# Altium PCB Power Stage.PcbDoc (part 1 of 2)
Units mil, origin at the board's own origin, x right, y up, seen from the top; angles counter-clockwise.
Board outline 9000 x 8000 mil, 6 copper layers (Top Layer, Layer 1, Layer 2, Layer 3, Layer 4, Bottom Layer), stack 92.2 mil thick; 168 components, 72 nets, 534 pads, 347 vias.
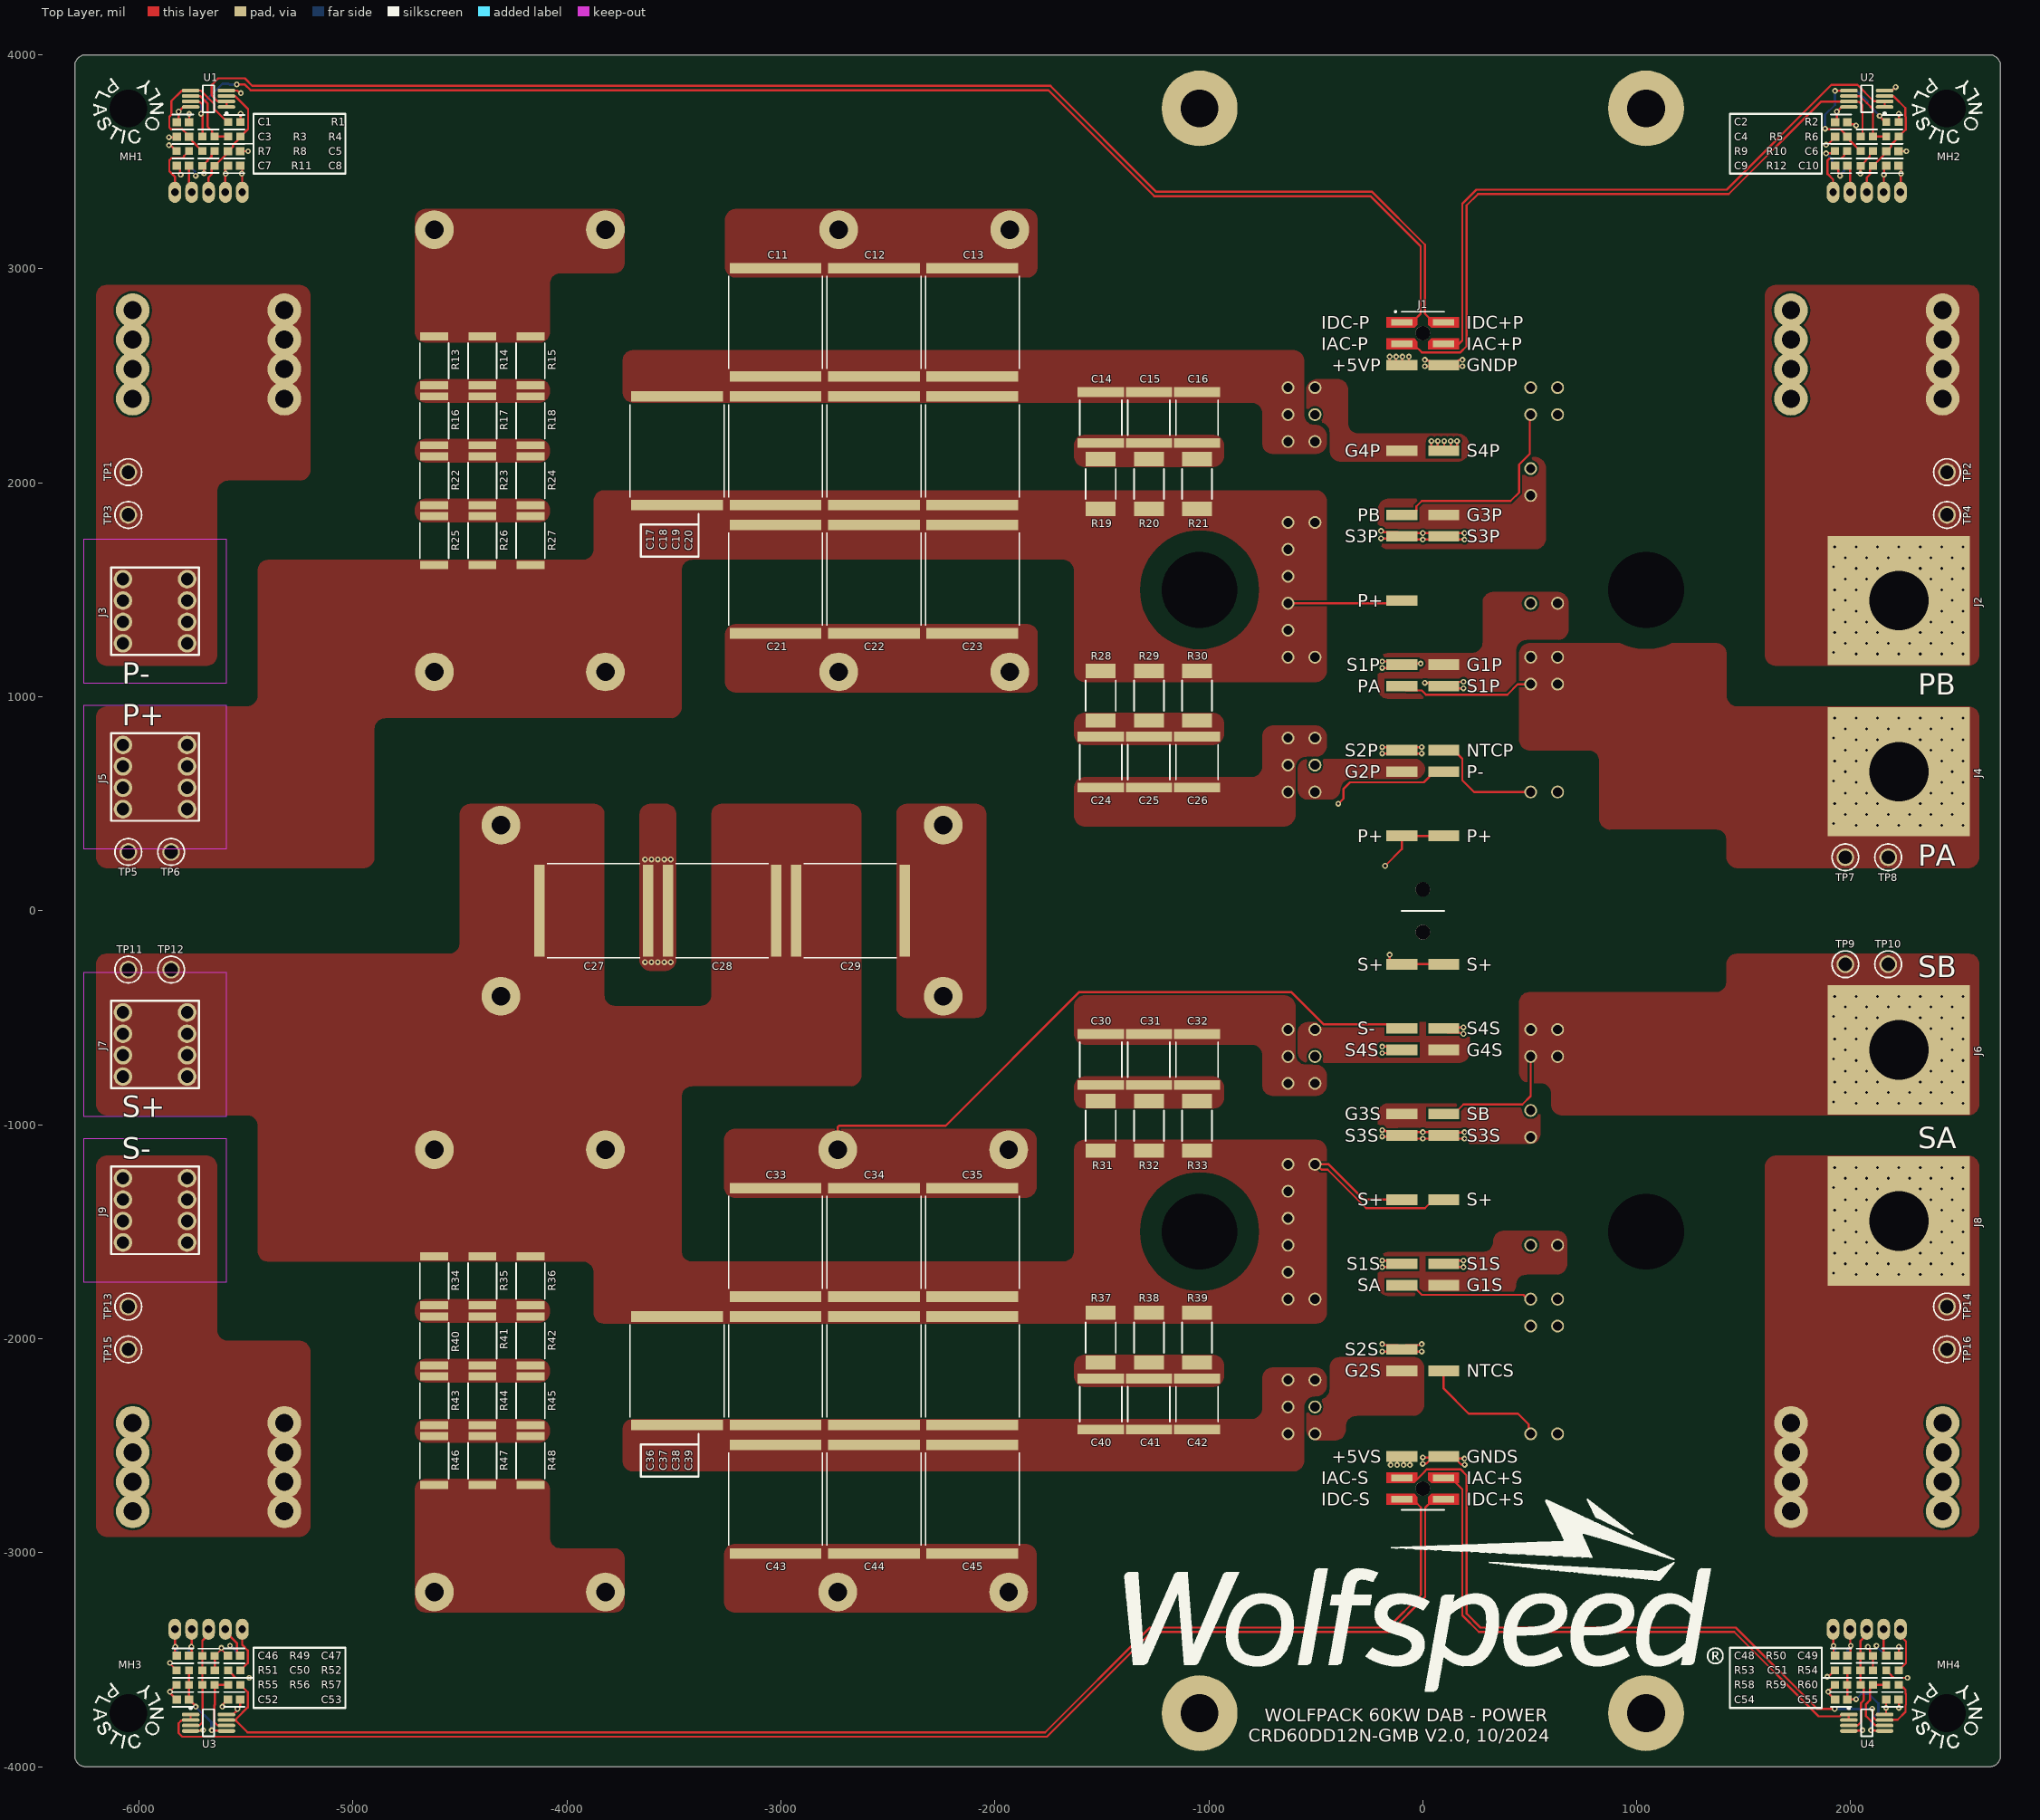
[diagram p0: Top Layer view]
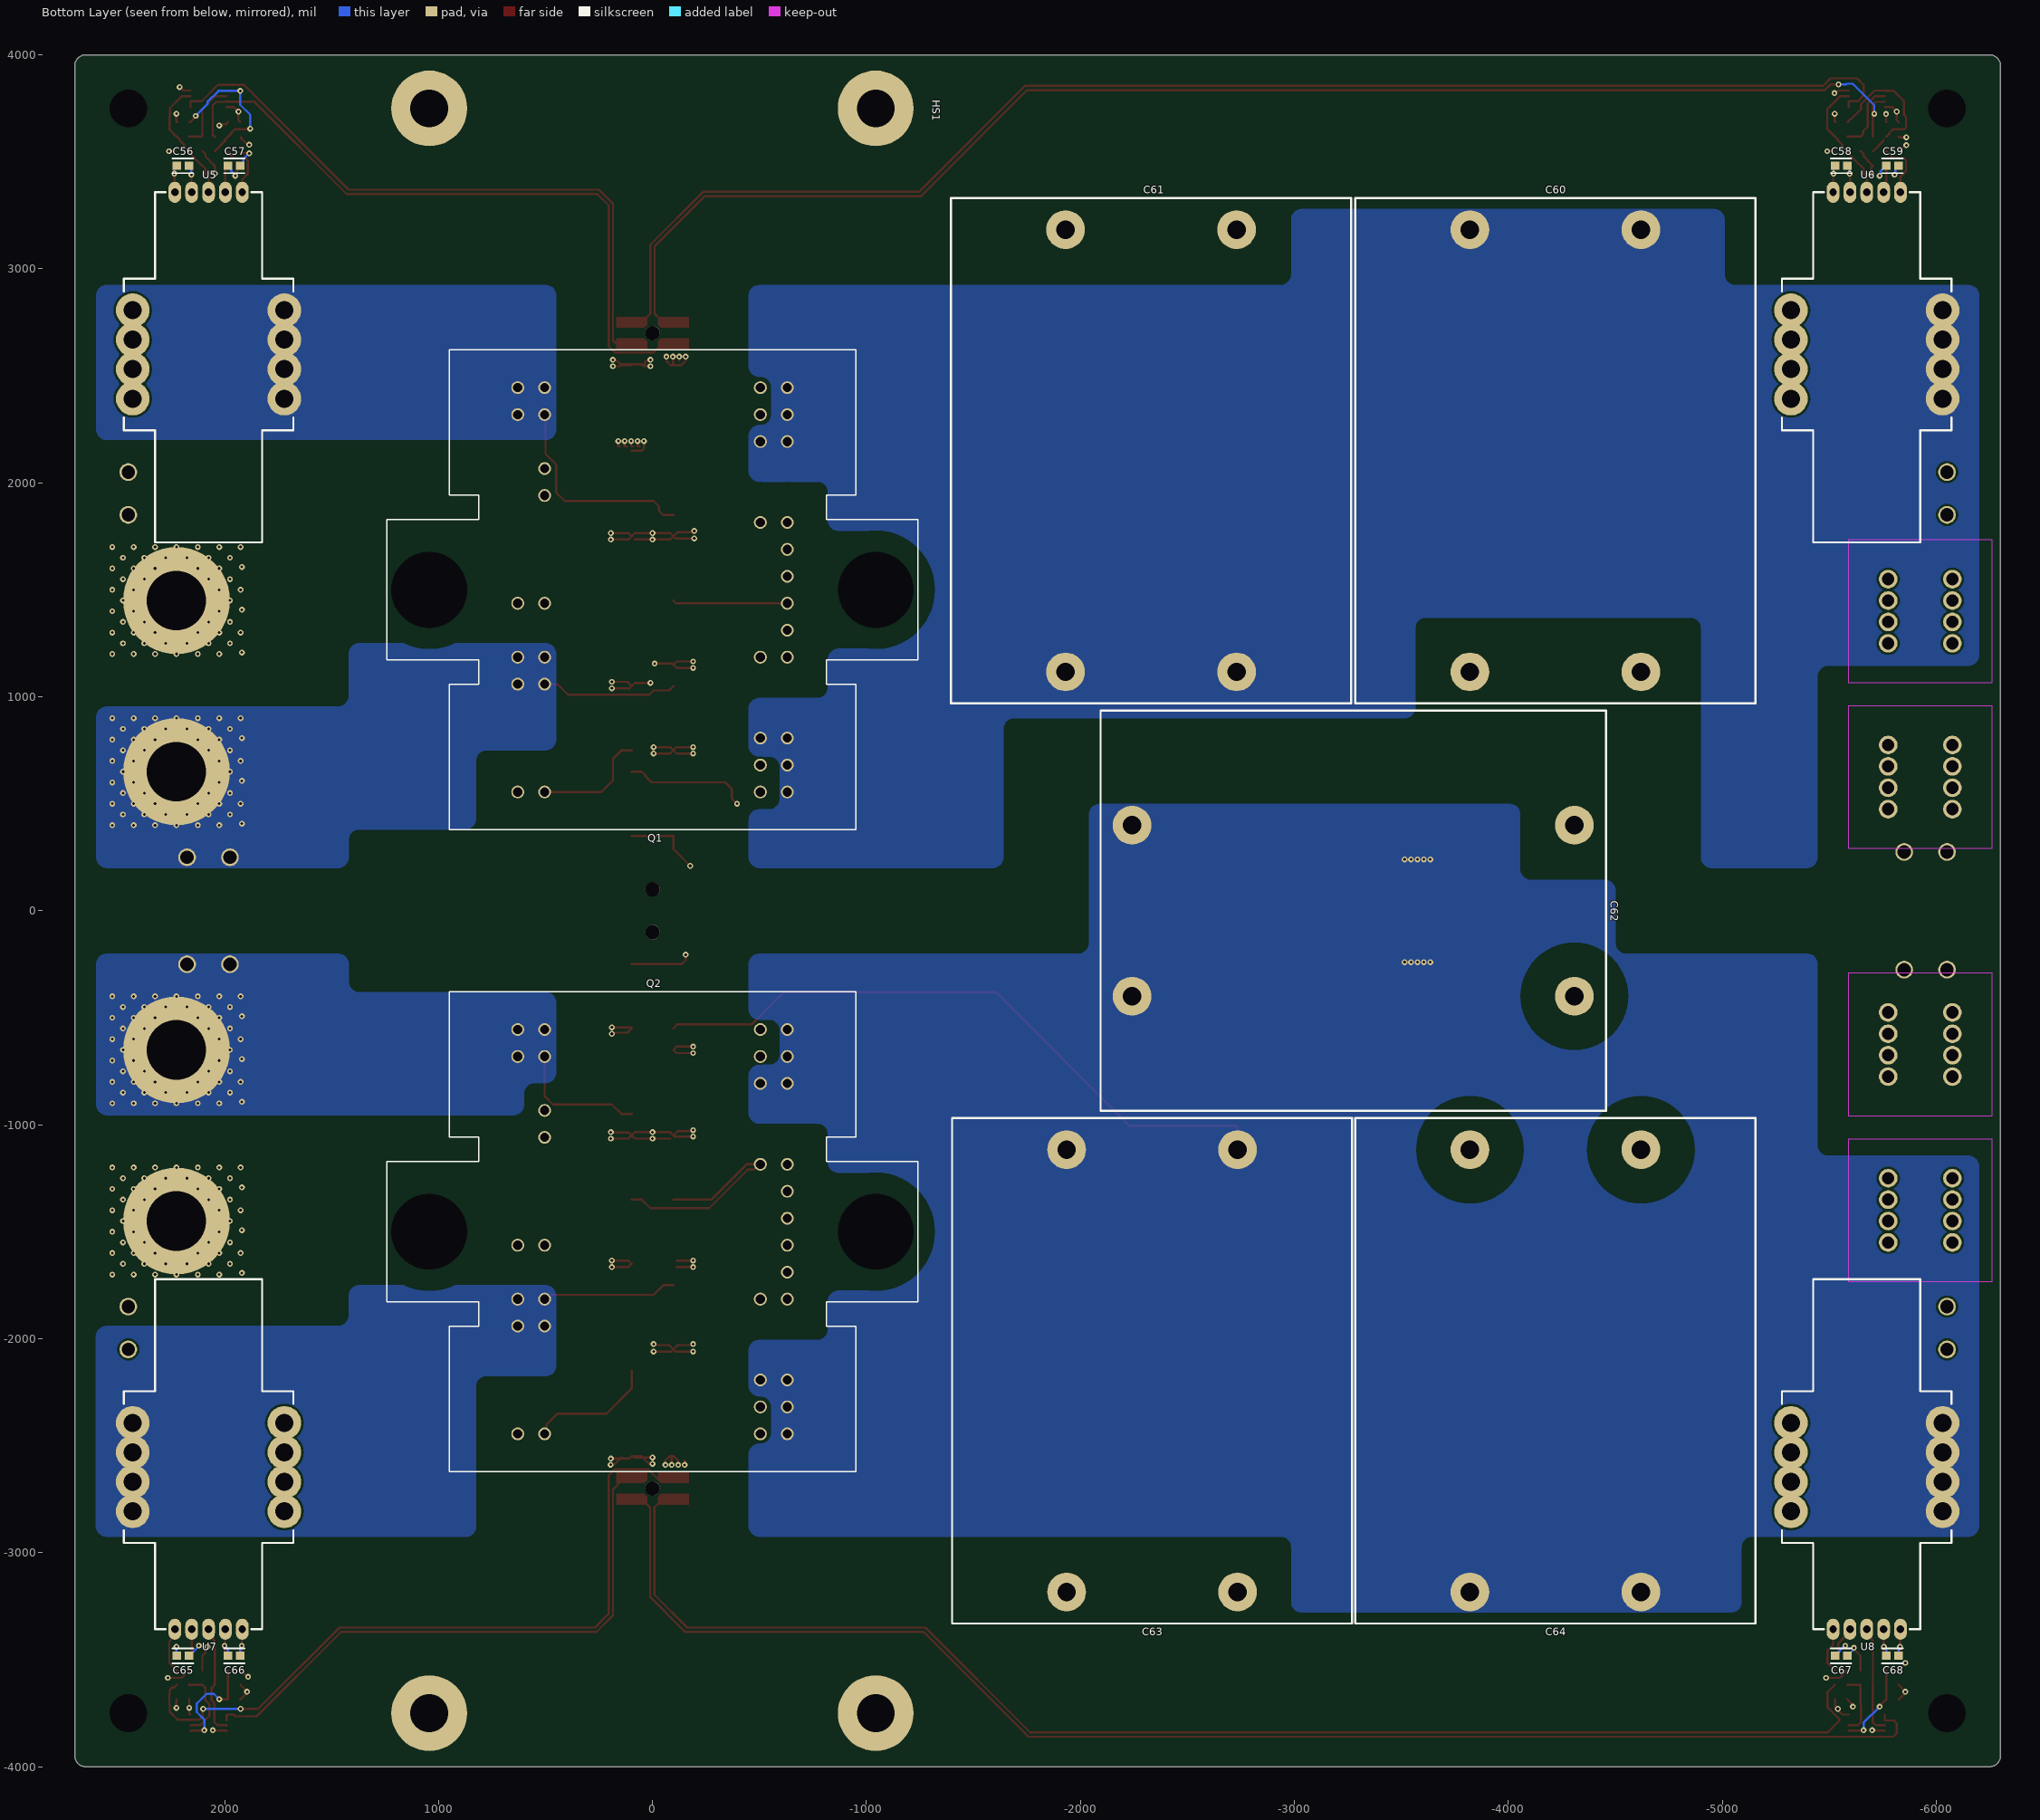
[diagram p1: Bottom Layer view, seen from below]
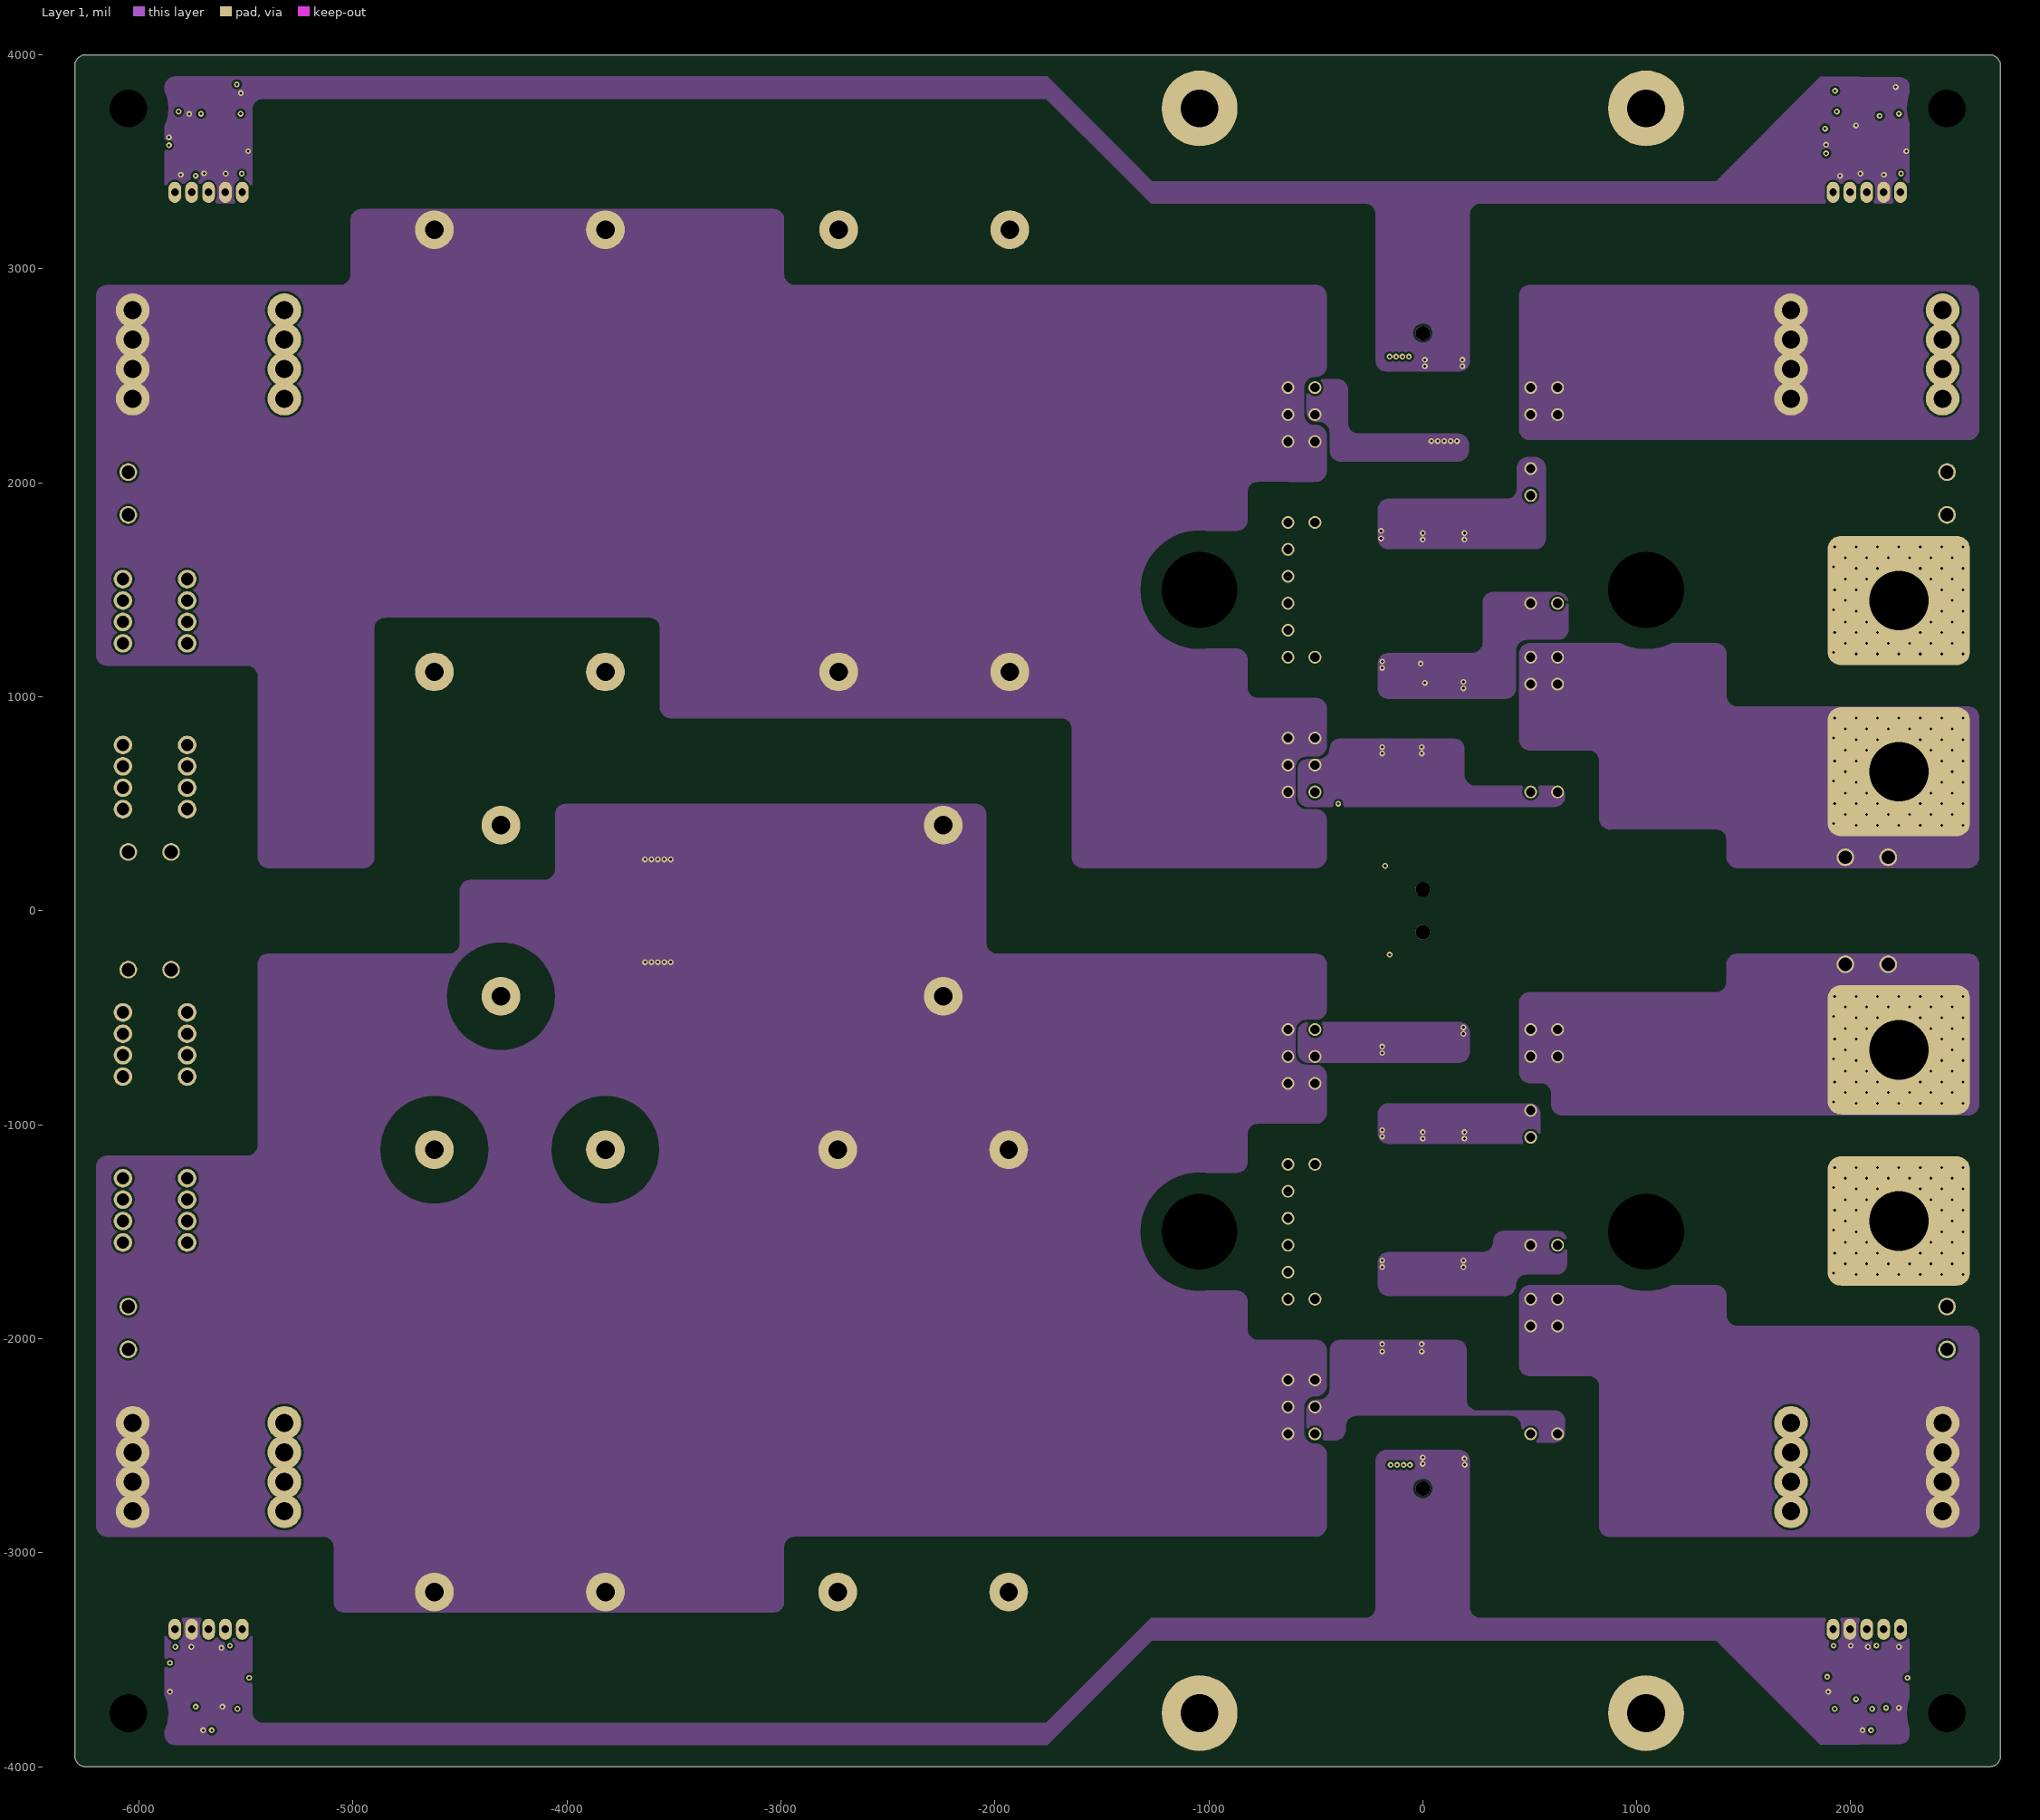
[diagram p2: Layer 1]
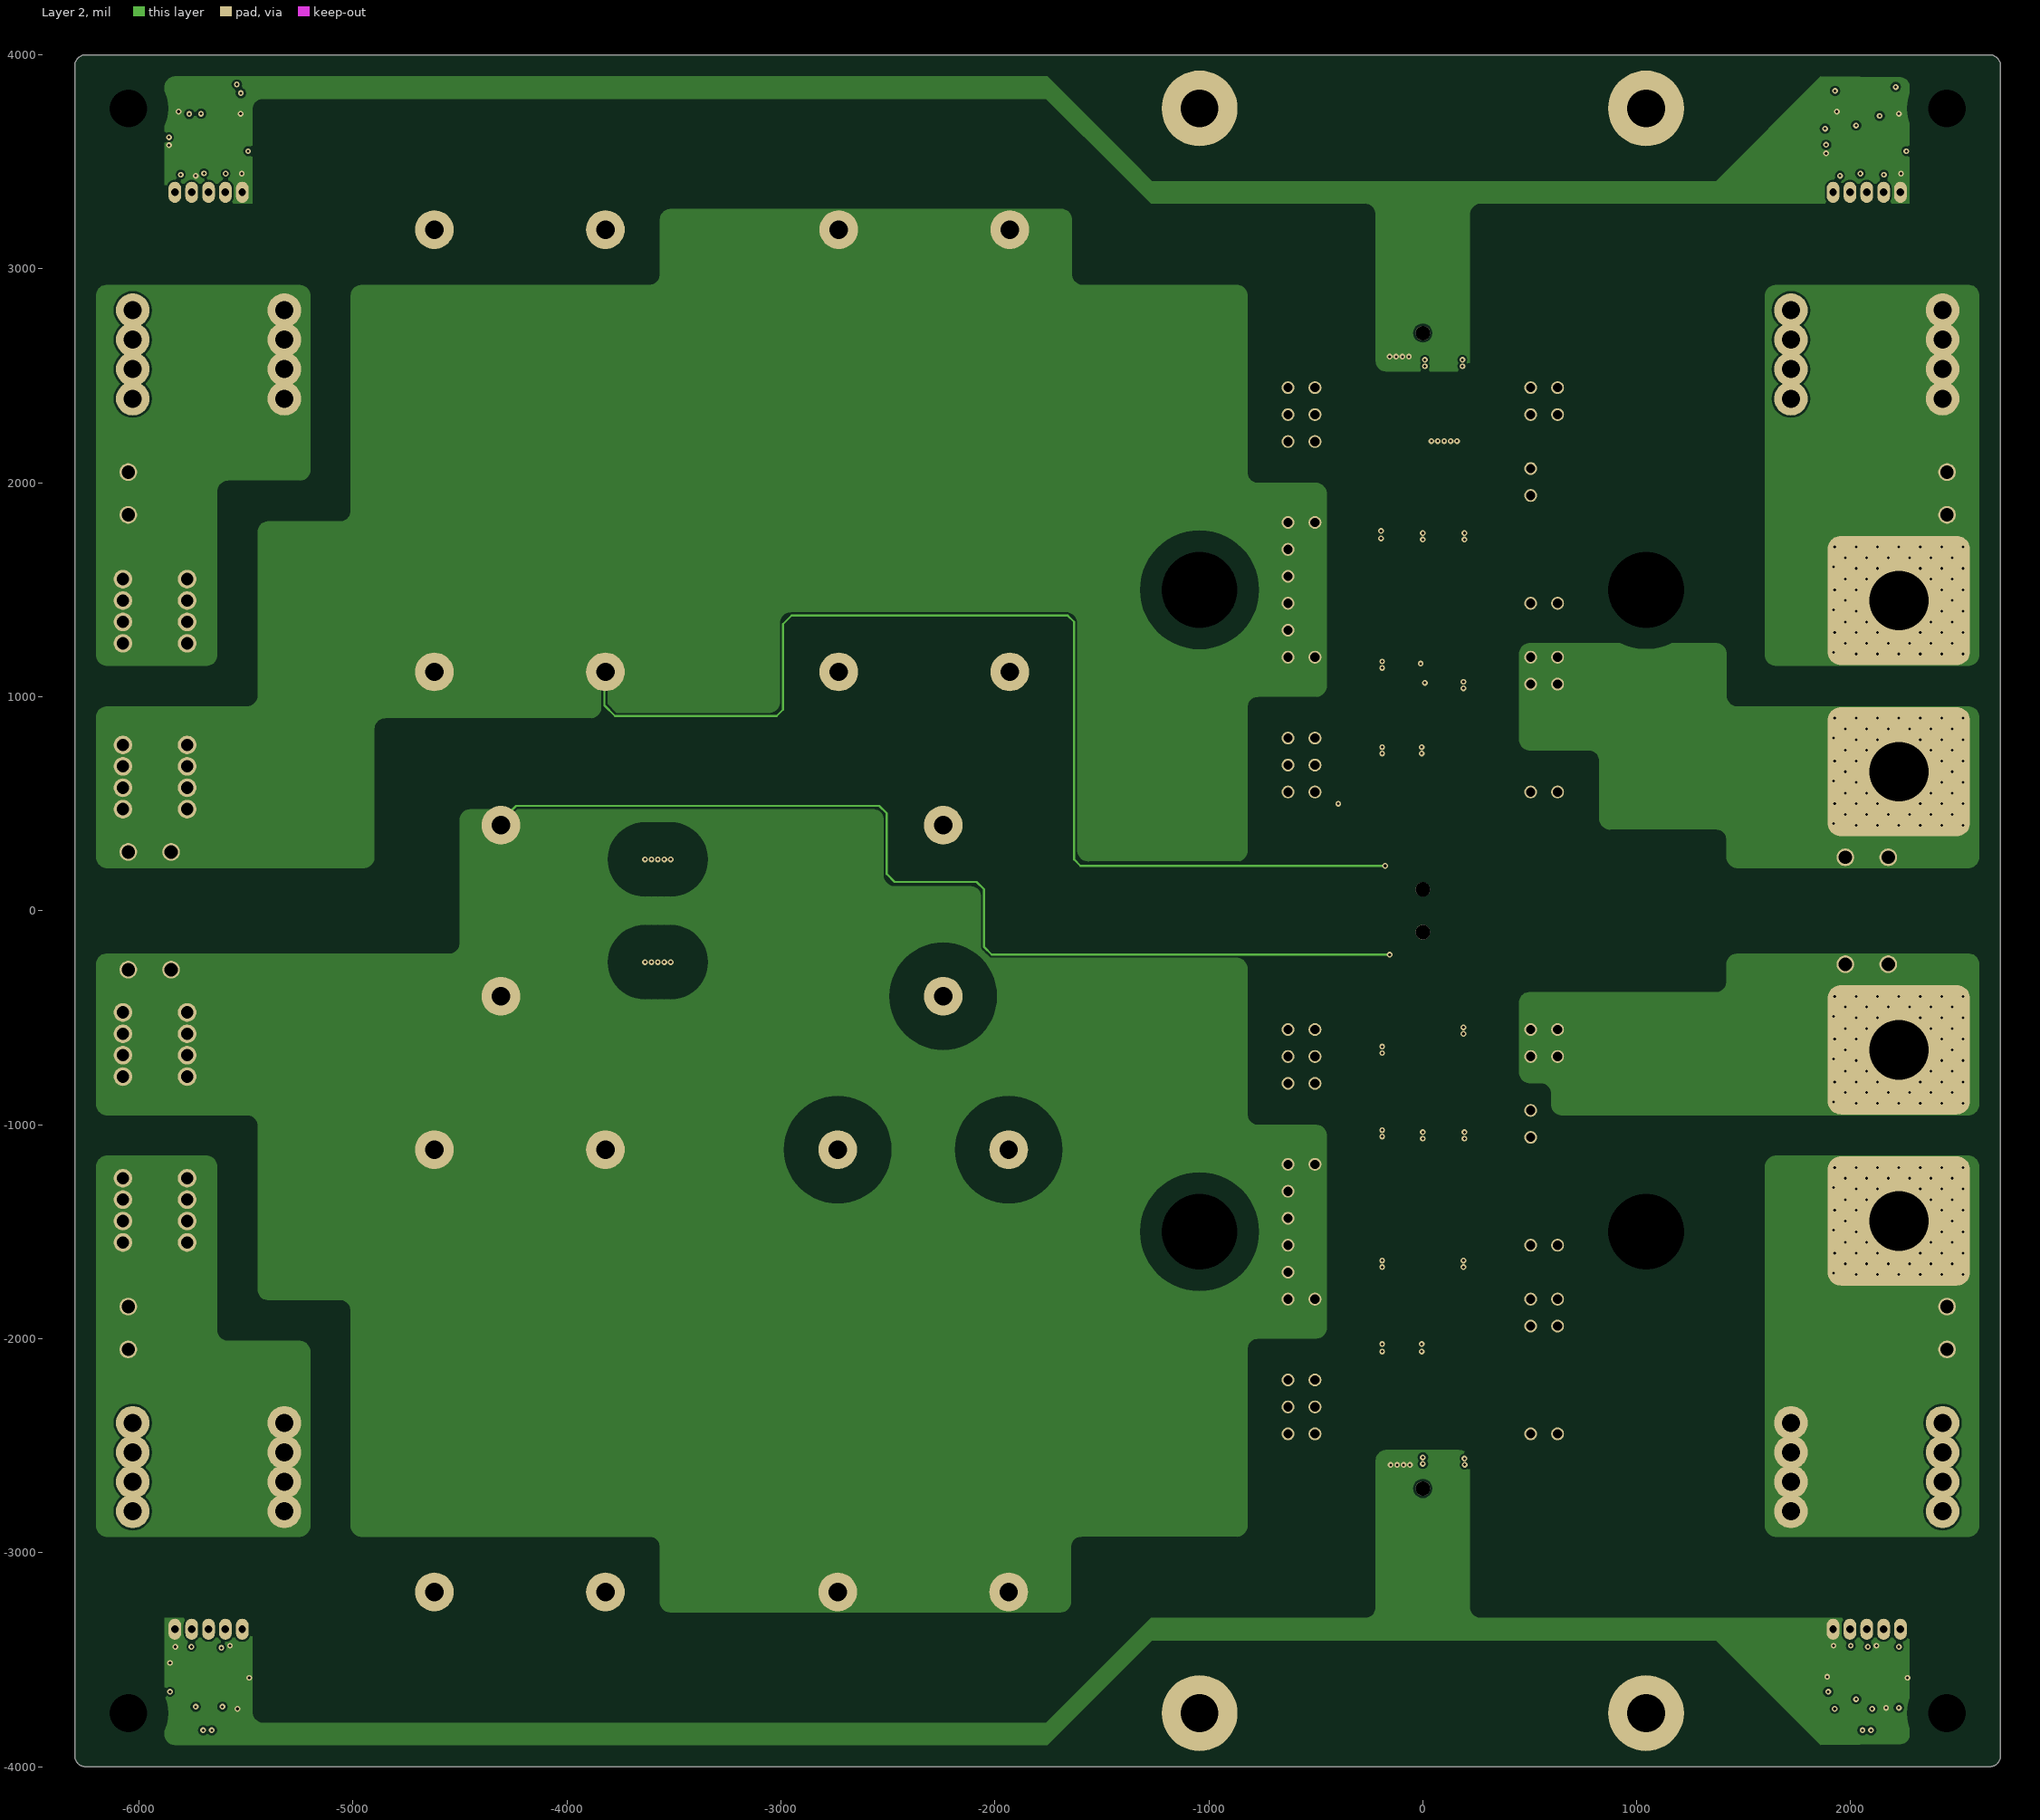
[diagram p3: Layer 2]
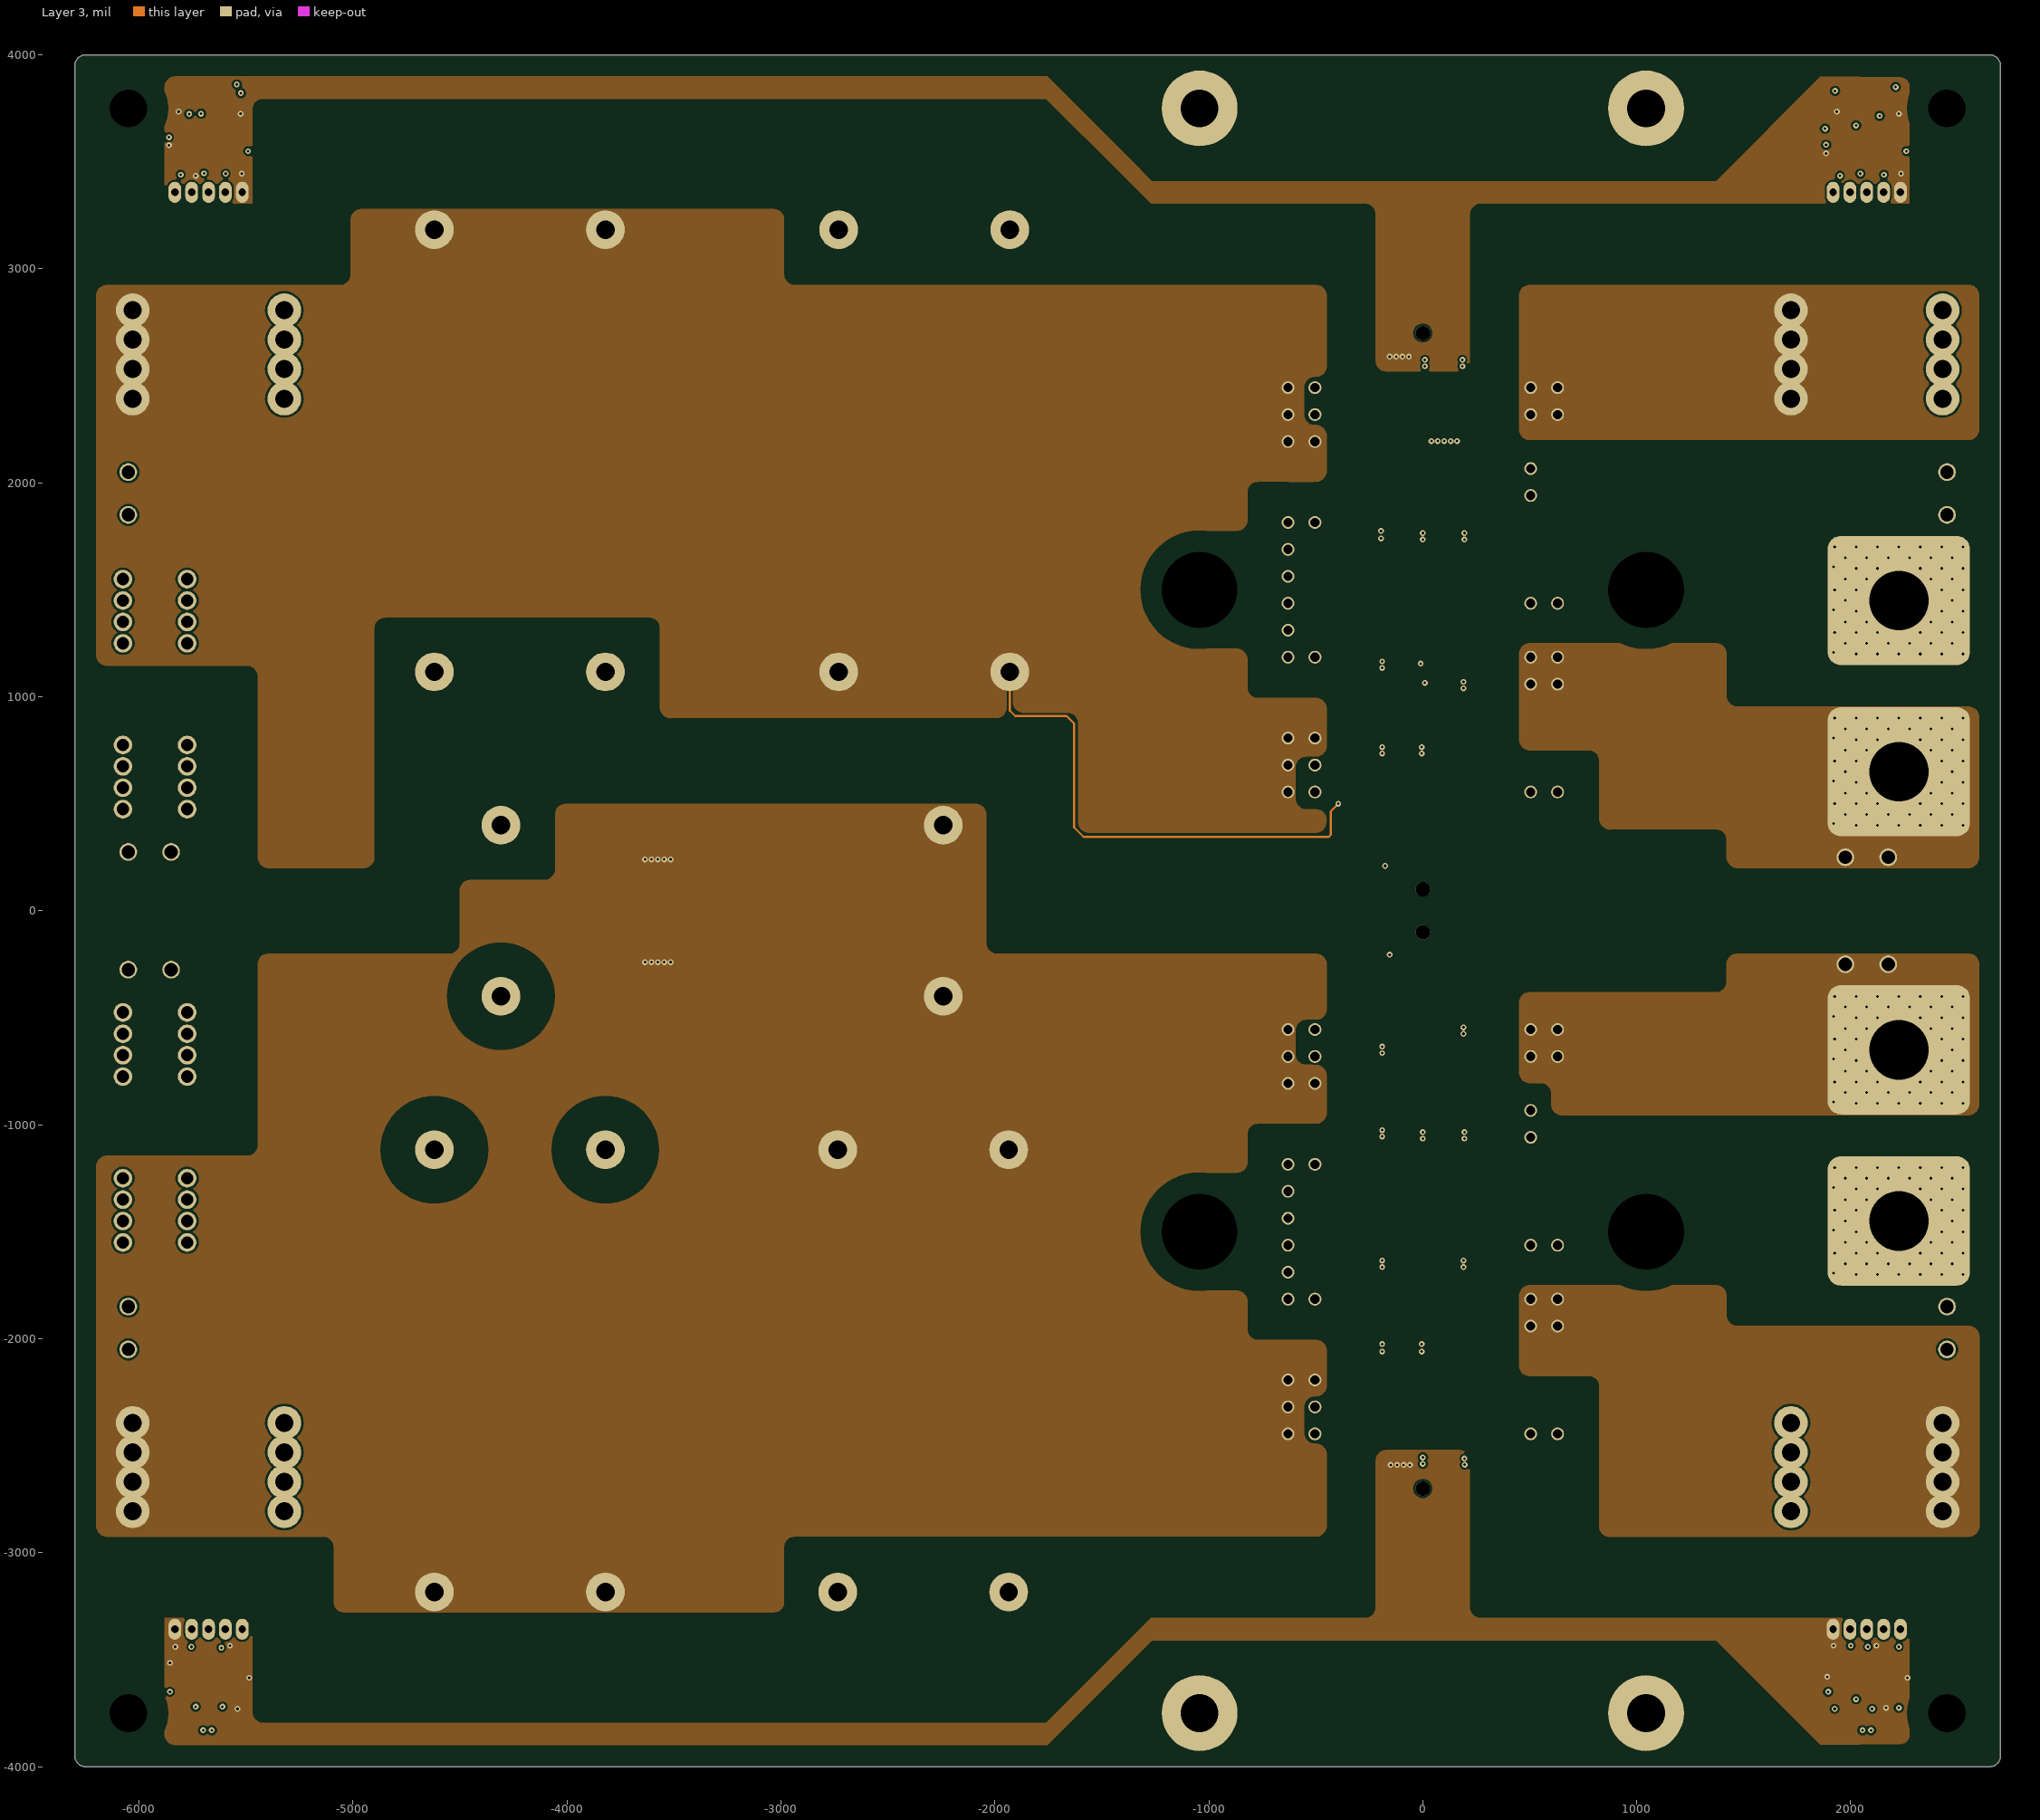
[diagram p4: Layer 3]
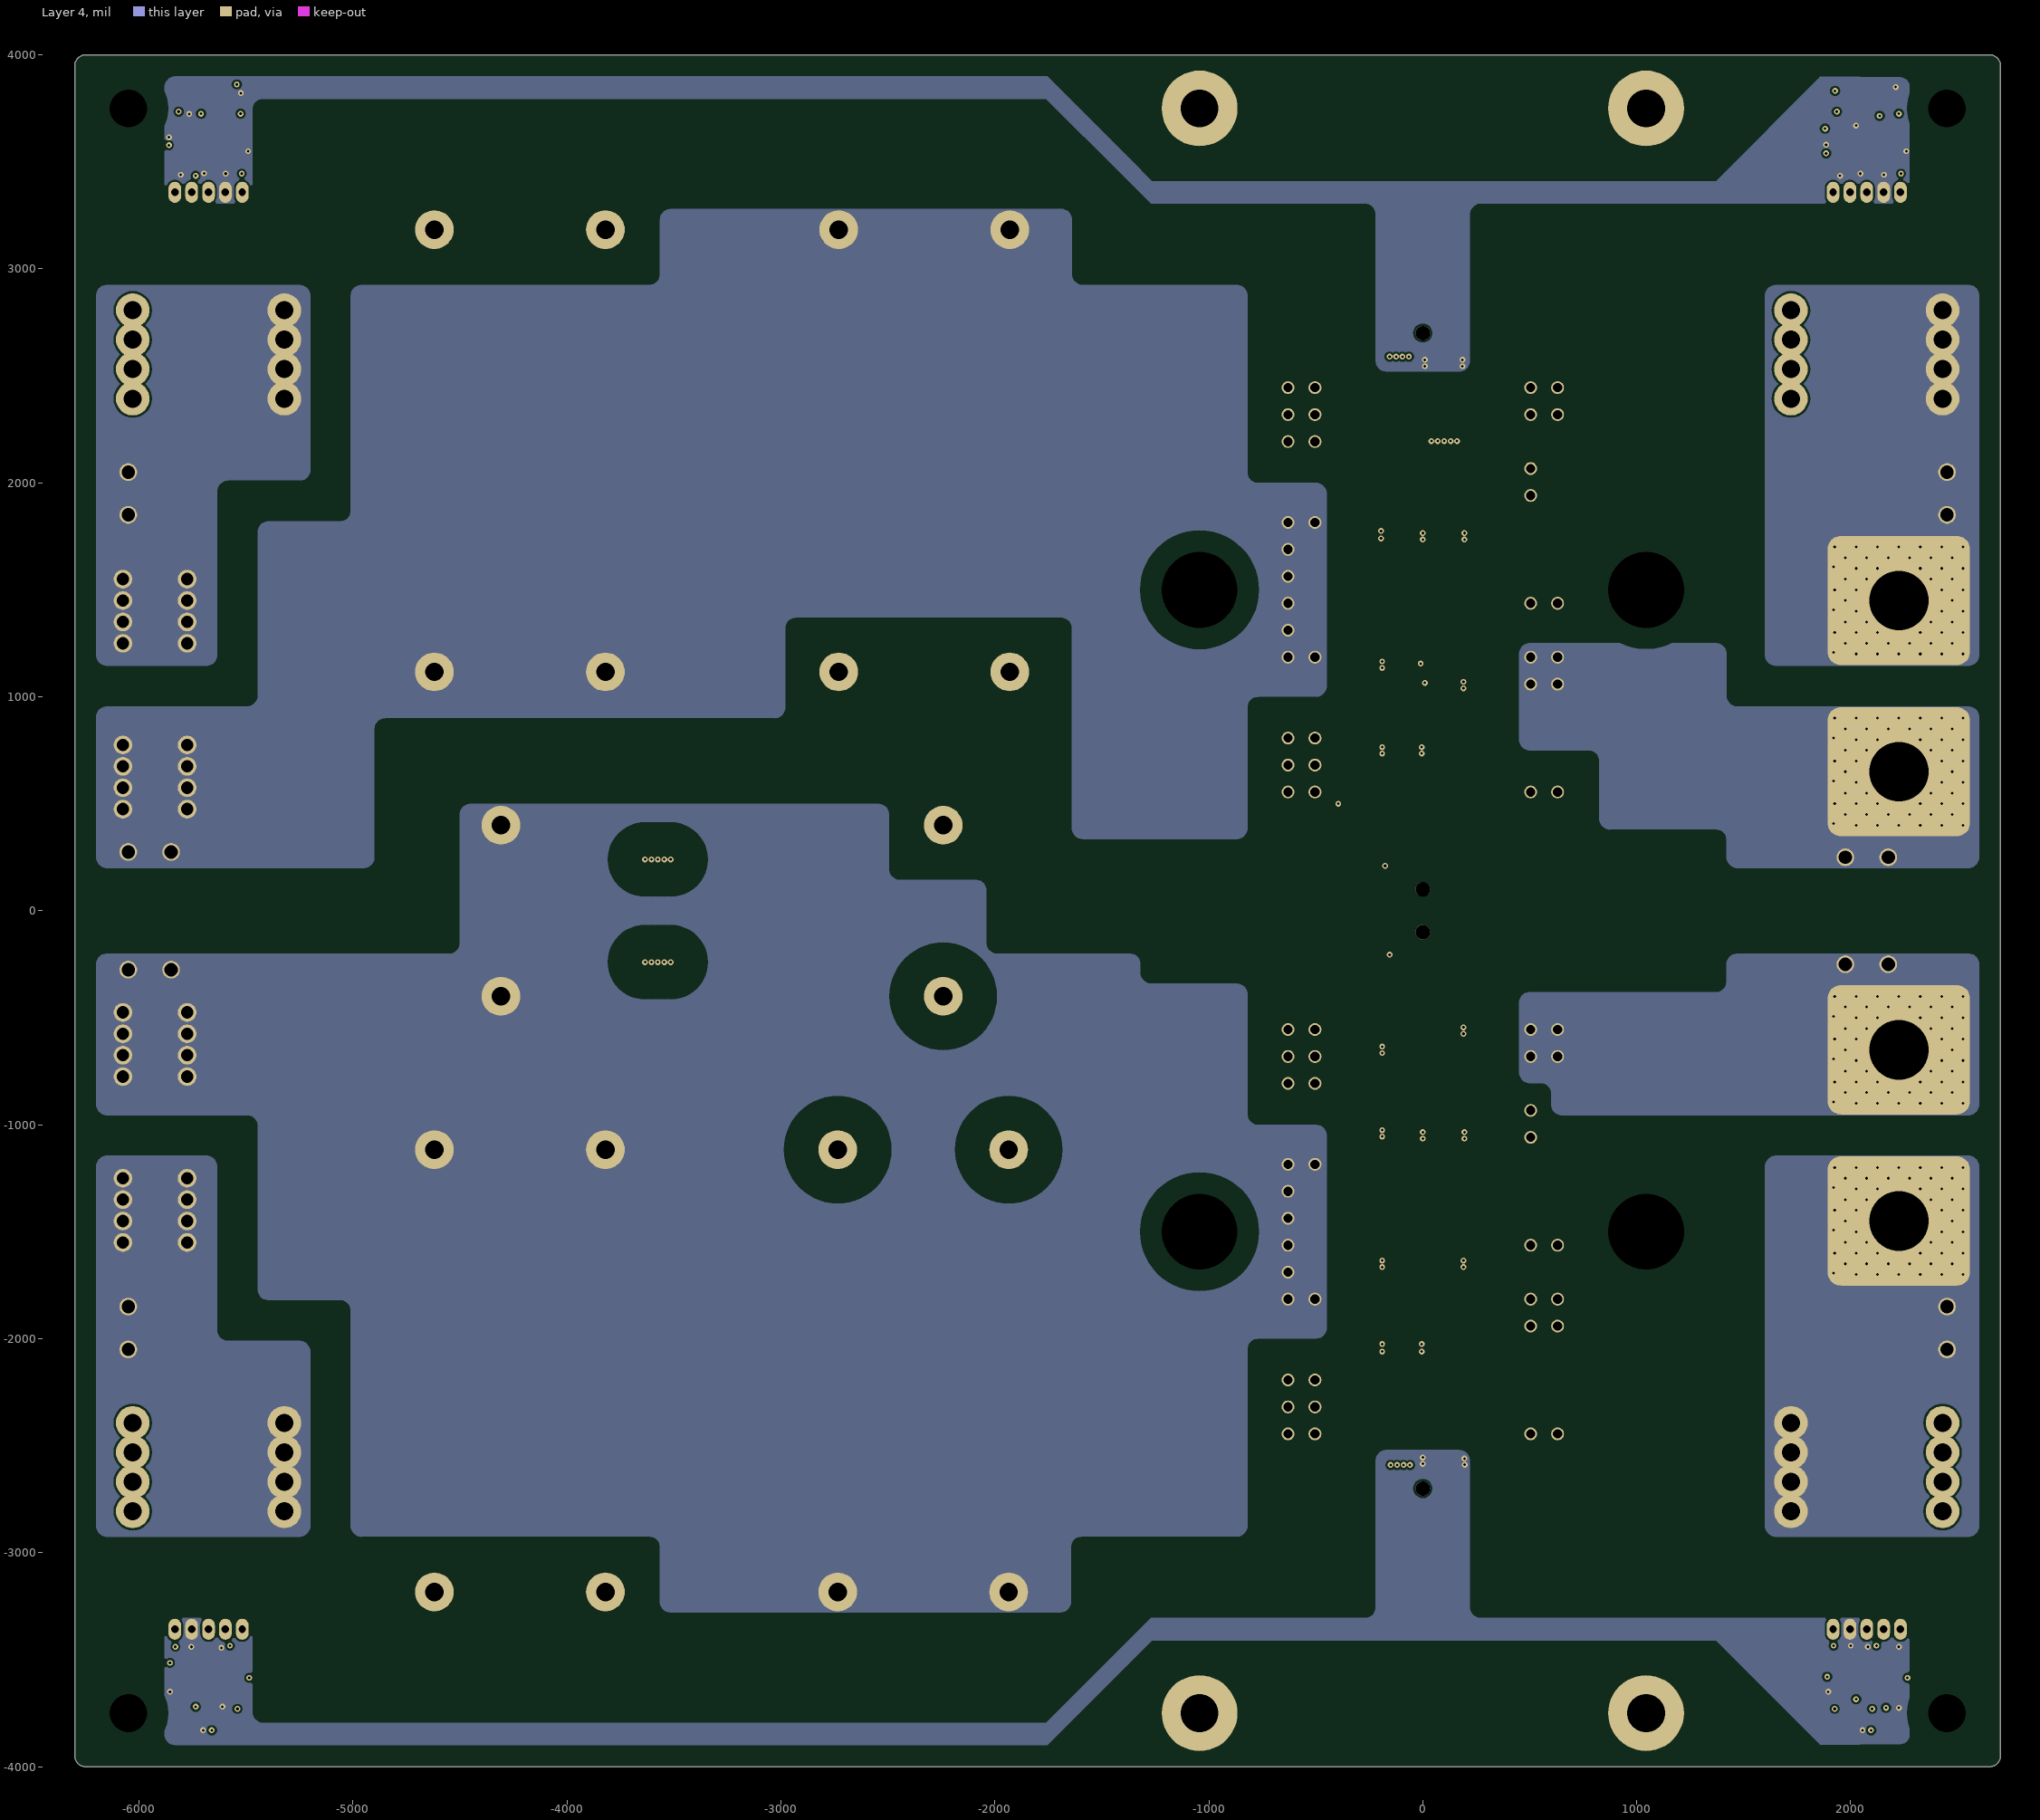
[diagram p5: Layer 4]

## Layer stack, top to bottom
Top Solder: solder mask 0.4, Solder Resist, Dk 3.5
Top Layer: signal copper 5.512
Dielectric 2: prepreg 10, PP-006, Dk 4.1
Layer 1: signal copper 5.512
Dielectric 4: prepreg 10, PP-006, Dk 4.1
Layer 2: signal copper 5.512
Dielectric 1: dielectric 19.128, FR-4, Dk 4.8
Layer 3: signal copper 5.512
Dielectric 5: prepreg 10, PP-006, Dk 4.1
Layer 4: signal copper 5.512
Dielectric 3: prepreg 10, PP-006, Dk 4.1
Bottom Layer: signal copper 5.512
Bottom Solder: solder mask 0.4, Solder Resist, Dk 3.5

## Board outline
-6250,-4000 cw(c-6250,-3950) -6300,-3950 -6300,3950 cw(c-6250,3950) -6250,4000 2650,4000 cw(c2650,3950) 2700,3950 2700,-3950 cw(c2650,-3950) 2650,-4000

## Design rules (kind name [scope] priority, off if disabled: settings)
AssemblyTestPointUsage [All] p1: isadvanced=TRUE
AssemblyTestpoint [All] p1: isadvanced=TRUE testpointundercomponent=TRUE minsize=40 maxsize=100 preferedsize=60 minholesize=0 maxholesize=40 preferedholesize=32 testpointgrid=1 usegrid=TRUE gridtolerance=0.01 allowsidetop=TRUE allowsidebottom=TRUE
Clearance "GD Hole to LV" [InNetClass('LV_CLASS') vs HoleDiameter = 68.11] p1: gap=10 ignorepadtopadclearanceinfootprint=FALSE
Clearance "GD Hole to S+" [InNet('S+') vs HoleDiameter = 68.11] p2: gap=90 ignorepadtopadclearanceinfootprint=FALSE
Clearance "LV to LV" [InNetClass('LV_CLASS') vs InNetClass('LV_CLASS')] p3: gap=10 ignorepadtopadclearanceinfootprint=TRUE
Clearance SNBS [InNetClass('SNBS_CLASS') vs InNetClass('S+_CLASS') Or InNetClass('S-_CLASS')] p4: gap=80 ignorepadtopadclearanceinfootprint=FALSE except(10: Arc-Hole Track-Hole SMDPad-Hole THPad-Hole Via-Hole Fill-Hole Poly-Hole Region-Hole Text-Hole)
Clearance SNBP [InNetClass('SNBP_CLASS') vs InNetClass('P+_CLASS') Or InNetClass('P-_CLASS')] p5: gap=80 ignorepadtopadclearanceinfootprint=FALSE except(10: Arc-Hole Track-Hole SMDPad-Hole THPad-Hole Via-Hole Fill-Hole Poly-Hole Region-Hole Text-Hole)
Clearance BLDS [InNetClass('BLDS_CLASS') vs InNetClass('S+_CLASS') Or InNetClass('S-_CLASS')] p6: gap=80 ignorepadtopadclearanceinfootprint=FALSE except(10: Arc-Hole Track-Hole SMDPad-Hole THPad-Hole Via-Hole Fill-Hole Poly-Hole Region-Hole Text-Hole)
Clearance BLDP [InNetClass('BLDP_CLASS') vs InNetClass('P+_CLASS') Or InNetClass('P-_CLASS')] p7: gap=80 ignorepadtopadclearanceinfootprint=FALSE except(10: Arc-Hole Track-Hole SMDPad-Hole THPad-Hole Via-Hole Fill-Hole Poly-Hole Region-Hole Text-Hole)
Clearance "SB to SB" [InNetClass('SB_CLASS') vs InNetClass('SB_CLASS')] p8: gap=10 ignorepadtopadclearanceinfootprint=FALSE
Clearance "SA to SA" [InNetClass('SA_CLASS') vs InNetClass('SA_CLASS')] p9: gap=10 ignorepadtopadclearanceinfootprint=FALSE
Clearance "PB to PB" [InNetClass('PB_CLASS') vs InNetClass('PB_CLASS')] p10: gap=10 ignorepadtopadclearanceinfootprint=FALSE
Clearance "PA to PA" [InNetClass('PA_CLASS') vs InNetClass('PA_CLASS')] p11: gap=10 ignorepadtopadclearanceinfootprint=FALSE
Clearance "S+ to S+" [InNetClass('S+_CLASS') vs InNetClass('S+_CLASS')] p12: gap=10 ignorepadtopadclearanceinfootprint=TRUE
Clearance "S- to S-" [InNetClass('S-_CLASS') vs InNetClass('S-_CLASS')] p13: gap=10 ignorepadtopadclearanceinfootprint=TRUE
Clearance "P+ to P+" [InNetClass('P+_CLASS') vs InNetClass('P+_CLASS')] p14: gap=10 ignorepadtopadclearanceinfootprint=TRUE
Clearance "P- to P-" [InNetClass('P-_CLASS') vs InNetClass('P-_CLASS')] p15: gap=10 ignorepadtopadclearanceinfootprint=TRUE
Clearance "Press-Fit Holes" [HasFootprint('7460307') vs HasFootprint('KSTN-5010_V') Or HasFootprint('KSTN-5011_V') Or HasFootprint('7460307')] p16: gap=0 ignorepadtopadclearanceinfootprint=TRUE
Clearance Default [All] p17: gap=160 ignorepadtopadclearanceinfootprint=TRUE except(100: Arc-Hole Track-Hole SMDPad-Hole THPad-Hole Via-Hole Fill-Hole Poly-Hole Region-Hole Text-Hole)
ComponentClearance [All] p1: isadvanced=TRUE gap=10 collisioncheckmode=3 verticalgap=10 showdistances=FALSE
FabricationTestPointUsage [All] p1: isadvanced=TRUE valid=0 allowmultiple=FALSE
FabricationTestpoint [All] p1: isadvanced=TRUE side=3 testpointundercomponent=TRUE minsize=40 maxsize=100 preferedsize=60 minholesize=0 maxholesize=40 preferedholesize=32 testpointgrid=1 allowsidetop=TRUE allowsidebottom=TRUE usegrid=TRUE gridtolerance=0.01
FanoutControl Fanout_Default [All] p1: isadvanced=TRUE bgadir=Out bgaviamode=Centered fanoutstyle=Auto fanoutdirection=Alternating viagrid=1 // Fanout_Default (Default Rule)
FanoutControl Fanout_Small [(CompPinCount < 5)] p2: isadvanced=TRUE bgadir=Out bgaviamode=Centered fanoutstyle=Auto fanoutdirection=OutThenIn viagrid=1 // Fanout_Small (Default Rule)
FanoutControl Fanout_SOIC [IsSOIC] p3: isadvanced=TRUE bgadir=Out bgaviamode=Centered fanoutstyle=Auto fanoutdirection=Alternating viagrid=1 // Fanout_SOIC (Default Rule)
FanoutControl Fanout_LCC [IsLCC] p4: isadvanced=TRUE bgadir=Out bgaviamode=Centered fanoutstyle=Auto fanoutdirection=Alternating viagrid=1 // Fanout_LCC (Default Rule)
FanoutControl Fanout_BGA [IsBGA] p5: isadvanced=TRUE bgadir=Out bgaviamode=Centered fanoutstyle=Auto fanoutdirection=Alternating viagrid=1 // Fanout_BGA (Default Rule)
Height [All] p1: isadvanced=TRUE minheight=0 maxheight=3000 prefheight=500
HoleSize [All] p1: isadvanced=TRUE absolutevalues=TRUE maxlimit=600 minlimit=1 maxpercent=80.000 minpercent=20.000
HoleToHoleClearance [All] p1: isadvanced=TRUE gap=10 allowstackedmicrovias=TRUE
LayerPairs [All] p1: isadvanced=TRUE enforce=TRUE
MinimumSolderMaskSliver [All] p1: isadvanced=TRUE minsoldermaskwidth=4
NetAntennae [All] p1: isadvanced=TRUE netantennaetolerance=0
PasteMaskExpansion [All] p1: isadvanced=TRUE expansion=0
PlaneClearance [All] p1: isadvanced=TRUE clearance=20
PlaneConnect [All] p1: isadvanced=TRUE planeconnectstyle=Relief reliefexpansion=20 reliefentries=4 reliefconductorwidth=10 reliefairgap=10
PolygonConnect [All] p1: connectstyle=Direct reliefconductorwidth=10 reliefentries=4 polygonreliefangle="90 Angle" airgapwidth=10
RoutingCorners [All] p1: isadvanced=TRUE cornerstyle=45-Degree minsetback=100 maxsetback=100
RoutingPriority [All] p1: isadvanced=TRUE routingpriority=0
RoutingVias [All] p1: holewidth=28 width=50 viastyle="Through Hole" minholewidth=28 minwidth=50 maxholewidth=28 maxwidth=50
ShortCircuit [All] p1: isadvanced=TRUE allowed=FALSE
SilkToSilkClearance [All] p1: isadvanced=TRUE silktosilkclearance=6
SilkToSolderMaskClearance [IsPad] p1: isadvanced=TRUE minsilkscreentomaskgap=6 clearancetoexposedcopper=TRUE
SolderMaskExpansion [All] p1: isadvanced=TRUE expansion=4 istentingtop=FALSE
SupplyNets "Schematic Supply Nets_7" [InNet('GND_P')] p1: voltage=0.000
SupplyNets "Schematic Supply Nets_6" [InNet('+5V_S')] p2: voltage=0.000
SupplyNets "Schematic Supply Nets_5" [InNet('GND_S')] p3: voltage=0.000
SupplyNets "Schematic Supply Nets_4" [InNet('+5V_P')] p4: voltage=0.000
SupplyNets "Schematic Supply Nets_3" [InNet('+5V_P')] p5: isadvanced=TRUE voltage=0.000
SupplyNets "Schematic Supply Nets_2" [InNet('GND_P')] p6: isadvanced=TRUE voltage=0.000
SupplyNets "Schematic Supply Nets_1" [InNet('GND_S')] p7: isadvanced=TRUE voltage=0.000
SupplyNets "Schematic Supply Nets" [InNet('+5V_S')] p8: isadvanced=TRUE voltage=0.000
UnRoutedNet [All] p1: isadvanced=TRUE
UnpouredPolygon [All] p1: isadvanced=TRUE
Width [All] p1: maxlimit=10 minlimit=10 preferedwidth=10
4 further rules are at their usual default settings.

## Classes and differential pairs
net class SNBS_CLASS: SNBS0 SNBS1
net class SNBP_CLASS: SNBP0 SNBP1
net class SB_CLASS: G3_S S3_S SB
net class SA_CLASS: G1_S S1_S SA SA_IO
net class PB_CLASS: G3_P PB PB_IO S3_P
net class PA_CLASS: G1_P PA S1_P
component class "Current Sense": C1 C2 C3 C4 C5 C6 C7 C8 C9 C10 C46 C47 C48 C49 C50 C51 C52 C53 C54 C55 C56 C57 C58 C59 C65 C66 C67 C68 R1 R2 R3 R4 R5 R6 R7 R8 R9 R10 R11 R12 R49 R50 R51 R52 R53 R54 R55 R56 R57 R58 R59 R60 U1 U2 U3 U4 U5 U6 U7 U8
component class "Power Stage": C11 C12 C13 C14 C15 C16 C17 C18 C19 C20 C21 C22 C23 C24 C25 C26 C27 C28 C29 C30 C31 C32 C33 C34 C35 C36 C37 C38 C39 C40 C41 C42 C43 C44 C45 C60 C61 C62 C63 C64 HS1 J1 J2 J3 J4 J5 J6 J7 J8 J9 MH1 MH2 MH3 MH4 Q1 Q2 R13 R14 R15 R16 R17 R18 R19 R20 R21 R22 R23 R24 R25 R26 R27 R28 R29 R30 R31 R32 R33 R34 R35 R36 R37 R38 R39 R40 R41 R42 R43 R44 R45 R46 R47 R48 TP1 TP2 TP3 TP4 TP5 TP6 TP7 TP8 TP9 TP10 TP11 TP12 TP13 TP14 TP15 TP16
net class BLDS_CLASS: BLDS0 BLDS1 BLDS2
net class BLDP_CLASS: BLDP0 BLDP1 BLDP2
net class LV_CLASS: +2.5V_P- +2.5V_PB +2.5V_S- +2.5V_SA +5V_P +5V_S FB_P- FB_PB FB_S- FB_SA GND_P GND_S IAC+_P IAC+_S IAC-_P IAC-_S IDC+_P IDC+_S IDC-_P IDC-_S OCD_P_ OCD_PB OCD_S- OCD_SA VO_P- VO_PB VO_S- VO_SA VREF_P- VREF_PB VREF_S- VREF_SA
net class S-_CLASS: G2_S G4_S NTC_S S2_S S4_S S- S-_IO
net class S+_CLASS: S+
net class P-_CLASS: G2_P G4_P NTC_P P- P-_IO S2_P S4_P
net class P+_CLASS: P+

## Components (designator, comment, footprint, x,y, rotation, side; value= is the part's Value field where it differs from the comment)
C1 "CGA3E2X7R1H104K080AA" FP-C0603C-CF-IPC_B -5795,3686 r0 top value=100nF (schematic designator C57)
C2 "CGA3E2X7R1H104K080AA" FP-C0603C-CF-IPC_B 1955,3686 r0 top value=100nF (schematic designator C49)
C3 "CGA3E2X7R1H104K080AA" FP-C0603C-CF-IPC_B -5795,3618 r180 top value=100nF (schematic designator C61)
C4 "CGA3E2X7R1H104K080AA" FP-C0603C-CF-IPC_B 1955,3618 r180 top value=100nF (schematic designator C51)
C5 "GCM188R72A103KA37D" FP-C0603C-CF-IPC_B -5555,3550 r0 top value=10nF (schematic designator C60)
C6 "GCM188R72A103KA37D" FP-C0603C-CF-IPC_B 2195,3550 r0 top value=10nF (schematic designator C50)
C7 "CGA3E2X7R1H473K080AA" FP-C0603C-CF-IPC_B -5795,3482 r180 top value=47nF (schematic designator C59)
C8 "CGA3E2X7R1H473K080AA" FP-C0603C-CF-IPC_B -5555,3482 r180 top value=47nF (schematic designator C58)
C9 "CGA3E2X7R1H473K080AA" FP-C0603C-CF-IPC_B 1955,3482 r180 top value=47nF (schematic designator C48)
C10 "CGA3E2X7R1H473K080AA" FP-C0603C-CF-IPC_B 2195,3482 r180 top value=47nF (schematic designator C43)
C11 "LDEQG2470KA5N00" CAP_LDE_QG_2470_KEM -3025,2750 r270 top value=0.047μF (schematic designator C30)
C12 "LDEQG2470KA5N00" CAP_LDE_QG_2470_KEM -2565,2750 r270 top value=0.047μF (schematic designator C31)
C13 "LDEQG2470KA5N00" CAP_LDE_QG_2470_KEM -2105,2750 r270 top value=0.047μF (schematic designator C32)
C14 "C2220C222KGRAC7800" FP-C5750-280-0_4-IPC_A -1505,2305 r90 top value=2.2nF (schematic designator C4)
C15 "C2220C222KGRAC7800" FP-C5750-280-0_4-IPC_A -1280,2305 r90 top value=2.2nF (schematic designator C5)
C16 "C2220C222KGRAC7800" FP-C5750-280-0_4-IPC_A -1055,2305 r90 top value=2.2nF (schematic designator C6)
C17 "LDEQG2470KA5N00" CAP_LDE_QG_2470_KEM -3485,2150 r90 top value=0.047μF (schematic designator C47)
C18 "LDEQG2470KA5N00" CAP_LDE_QG_2470_KEM -3025,2150 r90 top value=0.047μF (schematic designator C34)
C19 "LDEQG2470KA5N00" CAP_LDE_QG_2470_KEM -2565,2150 r90 top value=0.047μF (schematic designator C35)
C20 "LDEQG2470KA5N00" CAP_LDE_QG_2470_KEM -2105,2150 r90 top value=0.047μF (schematic designator C36)
C21 "LDEQG2470KA5N00" CAP_LDE_QG_2470_KEM -3025,1550 r270 top value=0.047μF (schematic designator C38)
C22 "LDEQG2470KA5N00" CAP_LDE_QG_2470_KEM -2565,1550 r270 top value=0.047μF (schematic designator C39)
C23 "LDEQG2470KA5N00" CAP_LDE_QG_2470_KEM -2105,1550 r270 top value=0.047μF (schematic designator C40)
C24 "C2220C222KGRAC7800" FP-C5750-280-0_4-IPC_A -1505,695 r270 top value=2.2nF (schematic designator C3)
C25 "C2220C222KGRAC7800" FP-C5750-280-0_4-IPC_A -1280,695 r270 top value=2.2nF (schematic designator C2)
C26 "C2220C222KGRAC7800" FP-C5750-280-0_4-IPC_A -1055,695 r270 top value=2.2nF (schematic designator C1)
C27 "LDEQG2470KA5N00" CAP_LDE_QG_2470_KEM -3875,0 r0 top value=0.047μF (schematic designator C44)
C28 "LDEQG2470KA5N00" CAP_LDE_QG_2470_KEM -3275,0 r180 top value=0.047μF (schematic designator C42)
C29 "LDEQG2470KA5N00" CAP_LDE_QG_2470_KEM -2675,0 r0 top value=0.047μF (schematic designator C45)
C30 "C2220C222KGRAC7800" FP-C5750-280-0_4-IPC_A -1505,-695 r90 top value=2.2nF (schematic designator C8)
C31 "C2220C222KGRAC7800" FP-C5750-280-0_4-IPC_A -1280,-695 r90 top value=2.2nF (schematic designator C9)
C32 "C2220C222KGRAC7800" FP-C5750-280-0_4-IPC_A -1055,-695 r90 top value=2.2nF (schematic designator C7)
C33 "LDEQG2470KA5N00" CAP_LDE_QG_2470_KEM -3025,-1550 r90 top value=0.047μF (schematic designator C26)
C34 "LDEQG2470KA5N00" CAP_LDE_QG_2470_KEM -2565,-1550 r90 top value=0.047μF (schematic designator C23)
C35 "LDEQG2470KA5N00" CAP_LDE_QG_2470_KEM -2105,-1550 r90 top value=0.047μF (schematic designator C15)
C36 "LDEQG2470KA5N00" CAP_LDE_QG_2470_KEM -3485,-2150 r270 top value=0.047μF (schematic designator C46)
C37 "LDEQG2470KA5N00" CAP_LDE_QG_2470_KEM -3025,-2150 r270 top value=0.047μF (schematic designator C24)
C38 "LDEQG2470KA5N00" CAP_LDE_QG_2470_KEM -2565,-2150 r270 top value=0.047μF (schematic designator C25)
C39 "LDEQG2470KA5N00" CAP_LDE_QG_2470_KEM -2105,-2150 r270 top value=0.047μF (schematic designator C28)
C40 "C2220C222KGRAC7800" FP-C5750-280-0_4-IPC_A -1505,-2305 r270 top value=2.2nF (schematic designator C12)
C41 "C2220C222KGRAC7800" FP-C5750-280-0_4-IPC_A -1280,-2305 r270 top value=2.2nF (schematic designator C11)
C42 "C2220C222KGRAC7800" FP-C5750-280-0_4-IPC_A -1055,-2305 r270 top value=2.2nF (schematic designator C10)
C43 "LDEQG2470KA5N00" CAP_LDE_QG_2470_KEM -3025,-2750 r90 top value=0.047μF (schematic designator C27)
C44 "LDEQG2470KA5N00" CAP_LDE_QG_2470_KEM -2565,-2750 r90 top value=0.047μF (schematic designator C17)
C45 "LDEQG2470KA5N00" CAP_LDE_QG_2470_KEM -2105,-2750 r90 top value=0.047μF (schematic designator C16)
C46 "CGA3E2X7R1H473K080AA" FP-C0603C-CF-IPC_B -5795,-3482 r0 top value=47nF (schematic designator C63)
C47 "CGA3E2X7R1H473K080AA" FP-C0603C-CF-IPC_B -5555,-3482 r180 top value=47nF (schematic designator C64)
C48 "CGA3E2X7R1H473K080AA" FP-C0603C-CF-IPC_B 1955,-3482 r0 top value=47nF (schematic designator C53)
C49 "CGA3E2X7R1H473K080AA" FP-C0603C-CF-IPC_B 2195,-3482 r0 top value=47nF (schematic designator C54)
C50 "GCM188R72A103KA37D" FP-C0603C-CF-IPC_B -5675,-3550 r0 top value=10nF (schematic designator C65)
C51 "GCM188R72A103KA37D" FP-C0603C-CF-IPC_B 2075,-3550 r0 top value=10nF (schematic designator C55)
C52 "CGA3E2X7R1H104K080AA" FP-C0603C-CF-IPC_B -5795,-3686 r180 top value=100nF (schematic designator C66)
C53 "CGA3E2X7R1H104K080AA" FP-C0603C-CF-IPC_B -5555,-3686 r180 top value=100nF (schematic designator C62)
C54 "CGA3E2X7R1H104K080AA" FP-C0603C-CF-IPC_B 1955,-3686 r180 top value=100nF (schematic designator C56)
C55 "CGA3E2X7R1H104K080AA" FP-C0603C-CF-IPC_B 2195,-3686 r0 top value=100nF (schematic designator C52)
C56 "GRT188R61H225ME13D" FP-C0603C-CF-IPC_B 2195,3482 r180 bottom value=2.2μF (schematic designator C70)
C57 "GRT188R61H225ME13D" FP-C0603C-CF-IPC_B 1955,3482 r0 bottom value=2.2μF (schematic designator C69)
C58 "GRT188R61H225ME13D" FP-C0603C-CF-IPC_B -5555,3482 r180 bottom value=2.2μF (schematic designator C68)
C59 "GRT188R61H225ME13D" FP-C0603C-CF-IPC_B -5795,3482 r180 bottom value=2.2μF (schematic designator C67)
C60 "C4AQNEW5650M3BJ" C4AQNEW5650M3BJ -4220,2150 r90 bottom locked value=65μF (schematic designator C22)
C61 "C4AQNEW5650M3BJ" C4AQNEW5650M3BJ -2330,2150 r270 bottom locked value=65μF (schematic designator C21)
C62 "C4AQNEW5650M3BJ" C4AQNEW5650M3BJ -3275,0 r0 bottom locked value=65μF (schematic designator C20)
C63 "C4AQNEW5650M3BJ" C4AQNEW5650M3BJ -2335,-2150 r90 bottom locked value=65μF (schematic designator C18)
C64 "C4AQNEW5650M3BJ" C4AQNEW5650M3BJ -4220,-2150 r270 bottom locked value=65μF (schematic designator C19)
C65 "GRT188R61H225ME13D" FP-C0603C-CF-IPC_B 2195,-3482 r0 bottom value=2.2μF (schematic designator C74)
C66 "GRT188R61H225ME13D" FP-C0603C-CF-IPC_B 1955,-3482 r0 bottom value=2.2μF (schematic designator C73)
C67 "GRT188R61H225ME13D" FP-C0603C-CF-IPC_B -5555,-3482 r180 bottom value=2.2μF (schematic designator C72)
C68 "GRT188R61H225ME13D" FP-C0603C-CF-IPC_B -5795,-3482 r0 bottom value=2.2μF (schematic designator C71)
HS1 "GM_FB_COLDPLATE" GM_FB_COLDPLATE 0,0 r180 bottom value=N/A
J1 "TSM-128-01-L-DV-A (X2)" SAMTEC_TSM-128-01-L-DV-A_DUAL_CUSTOM 0,0 r90 top value=N/A (schematic designator J3)
J2 "416N12" 4164N12 2225,1450 r90 top value=N/A
J3 "7460307" 7460307 -5925,1400 r90 top value=N/A (schematic designator J6)
J4 "416N12" 4164N12 2225,650 r90 top value=N/A (schematic designator J1)
J5 "7460307" 7460307 -5925,625 r90 top value=N/A (schematic designator J4)
J6 "416N12" 4164N12 2225,-650 r90 top value=N/A (schematic designator J9)
J7 "7460307" 7460307 -5925,-625 r90 top value=N/A
J8 "416N12" 4164N12 2225,-1450 r90 top value=N/A
J9 "7460307" 7460307 -5925,-1400 r90 top value=N/A (schematic designator J5)
MH1 "MH_M4_NP" MH_M4_NP -6050,3750 r0 top value=N/A (schematic designator MH3)
MH2 "MH_M4_NP" MH_M4_NP 2450,3750 r0 top value=N/A (schematic designator MH8)
MH3 "MH_M4_NP" MH_M4_NP -6050,-3750 r0 top value=N/A (schematic designator MH6)
MH4 "MH_M4_NP" MH_M4_NP 2450,-3750 r0 top value=N/A (schematic designator MH7)
Q1 "CBB011M12GM4" GM3_FULL-BRIDGE_CRW 0,1500 r270 bottom locked value=N/A
Q2 "CBB011M12GM4" GM3_FULL-BRIDGE_CRW 0,-1500 r270 bottom locked value=N/A
R1 "ERJ3EKF1002V" FP-MCR03-IPC_B -5555,3686 r0 top value=10kΩ (schematic designator R52)
R2 "ERJ3EKF1002V" FP-MCR03-IPC_B 2195,3686 r0 top value=10kΩ (schematic designator R40)
R3 "ERJ3EKF1002V" FP-MCR03-IPC_B -5675,3618 r0 top value=10kΩ (schematic designator R50)
R4 "ERJ3EKF1002V" FP-MCR03-IPC_B -5555,3618 r0 top value=10kΩ (schematic designator R51)
R5 "ERJ3EKF1002V" FP-MCR03-IPC_B 2075,3618 r0 top value=10kΩ (schematic designator R37)
R6 "ERJ3EKF1002V" FP-MCR03-IPC_B 2195,3618 r0 top value=10kΩ (schematic designator R39)
R7 "ERJ3EKF1002V" FP-MCR03-IPC_B -5795,3550 r180 top value=10kΩ (schematic designator R49)
R8 "ERJ3EKF1002V" FP-MCR03-IPC_B -5675,3550 r180 top value=10kΩ (schematic designator R54)
R9 "ERJ3EKF1002V" FP-MCR03-IPC_B 1955,3550 r180 top value=10kΩ (schematic designator R38)
R10 "ERJ3EKF1002V" FP-MCR03-IPC_B 2075,3550 r180 top value=10kΩ (schematic designator R42)
R11 "ERJ3EKF1002V" FP-MCR03-IPC_B -5675,3482 r0 top value=10kΩ (schematic designator R53)
R12 "ERJ3EKF1002V" FP-MCR03-IPC_B 2075,3482 r0 top value=10kΩ (schematic designator R41)
R13 "CRGP2512F220K" FP-CRGP2512-IPC_C -4620,2570 r270 top value=220kΩ (schematic designator R1)
R14 "CRGP2512F220K" FP-CRGP2512-IPC_C -4395,2570 r270 top value=220kΩ (schematic designator R4)
R15 "CRGP2512F220K" FP-CRGP2512-IPC_C -4170,2570 r270 top value=220kΩ (schematic designator R7)
R16 "CRGP2512F220K" FP-CRGP2512-IPC_C -4620,2290 r270 top value=220kΩ (schematic designator R2)
R17 "CRGP2512F220K" FP-CRGP2512-IPC_C -4395,2290 r270 top value=220kΩ (schematic designator R5)
R18 "CRGP2512F220K" FP-CRGP2512-IPC_C -4170,2290 r270 top value=220kΩ (schematic designator R8)
R19 "RPC2512JT6R80" FP-RMCF2512-IPC_A -1505,1995 r270 top value=6.8Ω (schematic designator R30)
R20 "RPC2512JT6R80" FP-RMCF2512-IPC_A -1280,1995 r270 top value=6.8Ω (schematic designator R29)
R21 "RPC2512JT6R80" FP-RMCF2512-IPC_A -1055,1995 r270 top value=6.8Ω (schematic designator R28)
R22 "CRGP2512F220K" FP-CRGP2512-IPC_C -4620,2010 r270 top value=220kΩ (schematic designator R3)
R23 "CRGP2512F220K" FP-CRGP2512-IPC_C -4395,2010 r270 top value=220kΩ (schematic designator R6)
R24 "CRGP2512F220K" FP-CRGP2512-IPC_C -4170,2010 r270 top value=220kΩ (schematic designator R9)
R25 "CRGP2512F220K" FP-CRGP2512-IPC_C -4620,1730 r270 top value=220kΩ (schematic designator R15)
R26 "CRGP2512F220K" FP-CRGP2512-IPC_C -4395,1730 r270 top value=220kΩ (schematic designator R14)
R27 "CRGP2512F220K" FP-CRGP2512-IPC_C -4170,1730 r270 top value=220kΩ (schematic designator R13)
R28 "RPC2512JT6R80" FP-RMCF2512-IPC_A -1505,1005 r90 top value=6.8Ω (schematic designator R25)
R29 "RPC2512JT6R80" FP-RMCF2512-IPC_A -1280,1005 r90 top value=6.8Ω (schematic designator R26)
R30 "RPC2512JT6R80" FP-RMCF2512-IPC_A -1055,1005 r90 top value=6.8Ω (schematic designator R27)
R31 "RPC2512JT6R80" FP-RMCF2512-IPC_A -1505,-1005 r270 top value=6.8Ω (schematic designator R33)
R32 "RPC2512JT6R80" FP-RMCF2512-IPC_A -1280,-1005 r270 top value=6.8Ω
R33 "RPC2512JT6R80" FP-RMCF2512-IPC_A -1055,-1005 r270 top value=6.8Ω (schematic designator R31)
R34 "CRGP2512F220K" FP-CRGP2512-IPC_C -4620,-1730 r90 top value=220kΩ (schematic designator R12)
R35 "CRGP2512F220K" FP-CRGP2512-IPC_C -4395,-1730 r90 top value=220kΩ (schematic designator R11)
R36 "CRGP2512F220K" FP-CRGP2512-IPC_C -4170,-1730 r90 top value=220kΩ (schematic designator R10)
R37 "RPC2512JT6R80" FP-RMCF2512-IPC_A -1505,-1995 r90 top value=6.8Ω (schematic designator R34)
R38 "RPC2512JT6R80" FP-RMCF2512-IPC_A -1280,-1995 r90 top value=6.8Ω (schematic designator R35)
R39 "RPC2512JT6R80" FP-RMCF2512-IPC_A -1055,-1995 r90 top value=6.8Ω (schematic designator R36)
R40 "CRGP2512F220K" FP-CRGP2512-IPC_C -4620,-2010 r90 top value=220kΩ (schematic designator R18)
R41 "CRGP2512F220K" FP-CRGP2512-IPC_C -4395,-2010 r90 top value=220kΩ (schematic designator R17)
R42 "CRGP2512F220K" FP-CRGP2512-IPC_C -4170,-2010 r90 top value=220kΩ (schematic designator R16)
R43 "CRGP2512F220K" FP-CRGP2512-IPC_C -4620,-2290 r90 top value=220kΩ (schematic designator R21)
R44 "CRGP2512F220K" FP-CRGP2512-IPC_C -4395,-2290 r90 top value=220kΩ (schematic designator R20)
R45 "CRGP2512F220K" FP-CRGP2512-IPC_C -4170,-2290 r90 top value=220kΩ (schematic designator R19)
R46 "CRGP2512F220K" FP-CRGP2512-IPC_C -4620,-2570 r90 top value=220kΩ (schematic designator R24)
R47 "CRGP2512F220K" FP-CRGP2512-IPC_C -4395,-2570 r90 top value=220kΩ (schematic designator R23)
R48 "CRGP2512F220K" FP-CRGP2512-IPC_C -4170,-2570 r90 top value=220kΩ (schematic designator R22)
R49 "ERJ3EKF1002V" FP-MCR03-IPC_B -5675,-3482 r180 top value=10kΩ (schematic designator R59)
R50 "ERJ3EKF1002V" FP-MCR03-IPC_B 2075,-3482 r180 top value=10kΩ (schematic designator R47)
R51 "ERJ3EKF1002V" FP-MCR03-IPC_B -5795,-3550 r180 top value=10kΩ (schematic designator R58)
R52 "ERJ3EKF1002V" FP-MCR03-IPC_B -5555,-3550 r180 top value=10kΩ (schematic designator R55)
R53 "ERJ3EKF1002V" FP-MCR03-IPC_B 1955,-3550 r180 top value=10kΩ (schematic designator R46)
R54 "ERJ3EKF1002V" FP-MCR03-IPC_B 2195,-3550 r180 top value=10kΩ (schematic designator R43)
R55 "ERJ3EKF1002V" FP-MCR03-IPC_B -5795,-3618 r0 top value=10kΩ (schematic designator R60)
R56 "ERJ3EKF1002V" FP-MCR03-IPC_B -5675,-3618 r180 top value=10kΩ (schematic designator R57)
R57 "ERJ3EKF1002V" FP-MCR03-IPC_B -5555,-3618 r180 top value=10kΩ (schematic designator R56)
R58 "ERJ3EKF1002V" FP-MCR03-IPC_B 1955,-3618 r0 top value=10kΩ (schematic designator R48)
R59 "ERJ3EKF1002V" FP-MCR03-IPC_B 2075,-3618 r180 top value=10kΩ (schematic designator R45)
R60 "ERJ3EKF1002V" FP-MCR03-IPC_B 2195,-3618 r180 top value=10kΩ (schematic designator R44)
TP1 "5011" KSTN-5011_V -6050,2050 r90 top value=BLACK (schematic designator TP15)
TP2 "5014" KSTN-5014_V 2450,2050 r180 top value=YELLOW (schematic designator TP5)
TP3 "5011" KSTN-5011_V -6050,1850 r90 top value=BLACK (schematic designator TP13)
TP4 "5014" KSTN-5014_V 2450,1850 r180 top value=YELLOW (schematic designator TP3)
TP5 "5010" KSTN-5010_V -6050,275 r0 top value=RED (schematic designator TP7)
TP6 "5010" KSTN-5010_V -5850,275 r0 top value=RED (schematic designator TP9)
TP7 "5012" KSTN-5012_V 1975,250 r0 top value=WHITE (schematic designator TP4)
TP8 "5012" KSTN-5012_V 2175,250 r0 top value=WHITE (schematic designator TP6)
TP9 "5014" KSTN-5014_V 1975,-250 r0 top value=YELLOW (schematic designator TP22)
TP10 "5014" KSTN-5014_V 2175,-250 r0 top value=YELLOW (schematic designator TP24)
TP11 "5010" KSTN-5010_V -6050,-275 r0 top value=RED (schematic designator TP17)
TP12 "5010" KSTN-5010_V -5850,-275 r0 top value=RED (schematic designator TP16)
TP13 "5011" KSTN-5011_V -6050,-1850 r90 top value=BLACK (schematic designator TP11)
TP14 "5012" KSTN-5012_V 2450,-1850 r0 top value=WHITE (schematic designator TP19)
TP15 "5011" KSTN-5011_V -6050,-2050 r90 top value=BLACK (schematic designator TP10)
TP16 "5012" KSTN-5012_V 2450,-2050 r0 top value=WHITE (schematic designator TP21)
U1 "AD8616ARMZ-REEL" ADI-RM-8_M -5675,3795 r180 top value=N/A (schematic designator U7)
U2 "AD8616ARMZ-REEL" ADI-RM-8_M 2075,3795 r180 top value=N/A (schematic designator U5)
U3 "AD8616ARMZ-REEL" ADI-RM-8_M -5675,-3795 r0 top value=N/A (schematic designator U8)
U4 "AD8616ARMZ-REEL" ADI-RM-8_M 2075,-3795 r0 top value=N/A (schematic designator U6)
U5 "HO 120-NP-0100" "HO xx0-NP-0100" 2075,2600 r90 bottom value=N/A (schematic designator U3)
U6 "HO 120-NP-0100" "HO xx0-NP-0100" -5675,2600 r90 bottom value=N/A (schematic designator U1)
U7 "HO 120-NP-0100" "HO xx0-NP-0100" 2075,-2600 r270 bottom value=N/A (schematic designator U4)
U8 "HO 120-NP-0100" "HO xx0-NP-0100" -5675,-2600 r270 bottom value=N/A (schematic designator U2)

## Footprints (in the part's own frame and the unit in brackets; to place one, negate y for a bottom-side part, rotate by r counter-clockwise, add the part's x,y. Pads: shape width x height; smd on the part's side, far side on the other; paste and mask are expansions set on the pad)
4164N12 [mil]
  rect 604x665 / inner rrect20% 604x665 / far side round 500 hole 278: 1(0,0)
  body extent -282,-312 282,312, height 688
7460307 [mm] "8 Pin Screw Terminal, Power Tap M4 Through Hole"
  round 2.21 hole 1.475: 1(-3.81,3.81) 2(-1.27,3.81) 3(1.27,3.81) 4(3.81,3.81) 5(3.81,-3.81) 6(1.27,-3.81) 7(-1.27,-3.81) 8(-3.81,-3.81)
  Top Layer keep-out region: -8.5,-8.5 8.5,-8.5 8.5,8.5 -8.5,8.5
  Bottom Layer keep-out region: -8.5,-8.5 8.5,-8.5 8.5,8.5 -8.5,8.5
  silkscreen extent -5.2,-5.2 5.2,5.2, body extent -4.5,-4.5 4.5,4.5, height 7
ADI-RM-8_M [mm] "SOP, 8-Leads, Body 3x3mm, Pitch 0.65mm, IPC Low Density"
  oval 2.1x0.45 smd: 1(-2.125,0.975) 2(-2.125,0.325) 3(-2.125,-0.325) 4(-2.125,-0.975) 5(2.125,-0.975) 6(2.125,-0.325) 7(2.125,0.325) 8(2.125,0.975)
  silkscreen extent -2.25,-1.6 0.67,1.87, body extent -1.6,-1.6 1.6,1.6, height 1.1
C4AQNEW5650M3BJ [mm]
  round 4.6 hole 2.2: 1A(-26.25,10.15) 1B(-26.25,-10.15) 2A(26.25,10.15) 2B(26.25,-10.15)
  silkscreen extent -30,-23.75 30,23.75, body extent -29.15,-22.81 29.15,22.7, height 65.3
CAP_LDE_QG_2470_KEM [mil]
  rect 49x429 smd paste+0 mask+0: 1(-253.5,0) 2(253.5,0)
  silkscreen extent -217,-220 217,220, body extent -264,-214 264,214, height 161
FP-C0603C-CF-IPC_B [mil]
  rect 39.63x37.73 smd paste+0 mask+0: 1(-28.58,0) 2(28.58,0)
  silkscreen extent -48,-35 48,35, body extent -58,-29 58,29, height 10
FP-C5750-280-0_4-IPC_A [mm]
  rect 1.153x5.503 smd paste+0 mask+0: 1(-3.025,0) 2(3.025,0)
  silkscreen extent -2.07,-2.5 2.07,2.5, body extent -4.1,-3.25 4.1,3.25, height 0.25
FP-CRGP2512-IPC_C [mil]
  rect 37.72x130.17 smd paste+0 mask+0: 1(-114.25,0) 2(114.25,0)
  silkscreen extent -84,-67 84,67, body extent -125,-63 125,63, height 26
FP-MCR03-IPC_B [mil]
  rect 37.72x35.91 smd paste+0 mask+0: 1(-28.62,0) 2(28.62,0)
  silkscreen extent -47,-34 47,34, body extent -57,-28 57,28, height 10
FP-RMCF2512-IPC_A [mil]
  rect 67.1x139.96 smd paste+0 mask+0: 1(-116.18,0) 2(116.18,0)
  silkscreen extent -71,-70 71,70, body extent -169,-90 169,90, height 10
GM3_FULL-BRIDGE_CRW [mm]
  round 1.524 hole 1.1: AC1_1(8,-12.8) AC1_2(11.2,-12.8) AC1_3(8,-16) AC1_4(11.2,-16) AC2_1(-24,-12.8) AC2_2(-20.8,-12.8) AC2_3(-24,-16) AC2_4(-20.8,-16) DC+_1(-8,16) DC+_2(-4.8,16) DC+_3(-1.6,16) DC+_4(1.6,16) DC+_5(4.8,16) DC+_6(8,16) DC+_7(-8,12.8) DC+_8(8,12.8) DC-1_1(17.6,16) DC-1_2(20.8,16) DC-1_3(24,16) DC-1_4(17.6,12.8) DC-2_1(-24,16) DC-2_2(-20.8,16) DC-2_3(-17.6,16) DC-2_4(-17.6,12.8) G1(1.6,-16) G2(24,12.8) G3(-11.2,-12.8) G4(-24,12.8) NTC1(24,-12.8) NTC2(24,-16) S1(1.6,-12.8) S2(20.8,12.8) S3(-14.4,-12.8) S4(-20.8,12.8)
  round 0 hole 9 unplated: MH1(0,26.5) MH2(0,-26.5)
  silkscreen extent -28.47,-31.52 28.47,31.52, body extent -28.38,-31.4 28.32,31.4, height 1.49
GM_FB_COLDPLATE [mm]
  round 9 hole 4.5: 1(-26.5,95.25) 2(26.5,95.25) 3(-26.5,-95.25) 4(26.5,-95.25)
  body extent -32.85,-101.6 32.85,101.6, height 24.46
"HO xx0-NP-0100" [mm]
  oval 2.5x1.5 hole 0.9: 1(19.25,4) 2(19.25,2) 3(19.25,0) 4(19.25,-2) 5(19.25,-4)
  round 4 hole 2.15: 6(5.25,-9) 7(1.75,-9) 8(-1.75,-9) 9(-5.25,-9) 10(-5.25,9) 11(-1.75,9) 12(1.75,9) 13(5.25,9)
  silkscreen extent -22.31,-10.07 19.25,10.07, body extent -23.11,-10.01 19.52,10.12, height 27.48
KSTN-5010_V [mm] "Test Point, Dia 3.17mm"
  round 2.1 hole 1.6: 1(0,0)
  silkscreen extent -1.59,-1.58 1.59,1.58, body extent -1.59,-1.59 1.59,1.59, height 8.13
KSTN-5011_V [mm] "Test Point, Dia 3.17mm"
  round 2.1 hole 1.6: 1(0,0)
  silkscreen extent -1.58,-1.59 1.58,1.59, body extent -1.59,-1.59 1.59,1.59, height 8.13
KSTN-5012_V [mm] "Test Point, Dia 3.17mm"
  round 2.1 hole 1.6: 1(0,0)
  silkscreen extent -1.59,-1.58 1.59,1.58, body extent -1.59,-1.59 1.59,1.59, height 8.13
KSTN-5014_V [mm] "Test Point, Dia 3.17mm"
  round 2.1 hole 1.6: 1(0,0)
  silkscreen extent -1.59,-1.58 1.59,1.58, body extent -1.59,-1.59 1.59,1.59, height 8.13
MH_M4_NP [mm] "M4 nonplated mounting hole"
  round 0 hole 4.5 unplated: 1(0,0)
  silkscreen extent -4.16,-4.16 4.19,3.6, body extent -4.62,-4 4.62,4, height 21
SAMTEC_TSM-128-01-L-DV-A_DUAL_CUSTOM [mm]
  rect 0.8x2.5 smd paste-2 mask+0: 001(69.85,2.475) 002(69.85,-2.475) 003(67.31,2.475) 004(67.31,-2.475) 109(-67.31,2.475) 110(-67.31,-2.475) 111(-69.85,2.475) 112(-69.85,-2.475)
  rect 1.27x3.68 smd: 005(64.77,2.475) 006(64.77,-2.475) 013(54.61,2.475) 014(54.61,-2.475) 019(46.99,2.475) 020(46.99,-2.475) 021(44.45,2.475) 022(44.45,-2.475) 027(36.83,2.475) 033(29.21,2.475) 034(29.21,-2.475) 035(26.67,2.475) 036(26.67,-2.475) 041(19.05,2.475) 042(19.05,-2.475) 043(16.51,2.475) 044(16.51,-2.475) 049(8.89,2.475) 050(8.89,-2.475) 061(-6.35,2.475) 062(-6.35,-2.475) 067(-13.97,2.475) 068(-13.97,-2.475) 069(-16.51,2.475) 070(-16.51,-2.475) 075(-24.13,2.475) 076(-24.13,-2.475) 077(-26.67,2.475) 078(-26.67,-2.475) 083(-34.29,2.475) 084(-34.29,-2.475) 089(-41.91,2.475) 090(-41.91,-2.475) 091(-44.45,2.475) 092(-44.45,-2.475) 097(-52.07,2.475) 099(-54.61,2.475) 100(-54.61,-2.475) 107(-64.77,2.475) 108(-64.77,-2.475)
  round 1.73 hole 1.73 unplated: ""(-68.58,0) ""(-2.54,0) ""(2.54,0) ""(68.58,0)
  Top Layer region: 67.945,-0.995 67.945,-4.315 66.675,-4.315 66.675,-0.635 67.585,-0.635
  Top Layer region: 67.945,0.995 67.585,0.635 66.675,0.635 66.675,4.315 67.945,4.315
  Top Layer region: 70.485,-4.315 69.215,-4.315 69.215,-0.995 69.575,-0.635 70.485,-0.635
  Top Layer region: 70.485,0.635 69.575,0.635 69.215,0.995 69.215,4.315 70.485,4.315
  Top Layer region: -69.215,-0.995 -69.215,-4.315 -70.485,-4.315 -70.485,-0.635 -69.575,-0.635
  Top Layer region: -69.215,0.995 -69.575,0.635 -70.485,0.635 -70.485,4.315 -69.215,4.315
  Top Layer region: -66.675,-4.315 -67.945,-4.315 -67.945,-0.995 -67.585,-0.635 -66.675,-0.635
  Top Layer region: -66.675,0.635 -67.585,0.635 -67.945,0.995 -67.945,4.315 -66.675,4.315
  silkscreen extent -71.12,-2.54 71.22,3.35, body extent -71.12,-3.81 71.12,3.89, height 9.66

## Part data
C1 C2 C3 C4 C52 C53 C54 C55: "CAP CER 0.1UF 50V X7R 0603", Capacitance=100nF, Case Code (Imperial)=0603, Case Code (Metric)=1608, Dielectric=X7R, Manufacturer=TDK, Max Operating Temperature=125°C, Min Operating Temperature=-55°C, Package Quantity=1, Ratings=AEC-Q200, TOLERANCE=10%, Voltage=50V
C5 C6 C50 C51: "CAP CER 10000PF 100V X7R 0603", Capacitance=10nF, Case Code (Imperial)=0603, Case Code (Metric)=1608, Dielectric=X7R, Manufacturer=MURATA, Max Operating Temperature=125°C, Min Operating Temperature=-55°C, Package Quantity=1, Ratings=AEC-Q200, Supplier Part Number 1=81-GCM188R72A103KA7D, TOLERANCE=10%, Voltage=100V
C7 C8 C9 C10 C46 C47 C48 C49: "CAP CER 0.047UF 50V X7R 0603", Capacitance=47nF, Case Code (Imperial)=0603, Case Code (Metric)=1608, Dielectric=X7R, Manufacturer=TDK, Max Operating Temperature=125°C, Min Operating Temperature=-55°C, Package Quantity=1, Ratings=AEC-Q200, Supplier Part Number 1=80X3178, TOLERANCE=10%, Voltage Rating=50V
C11 C12 C13 C17 C18 C19 C20 C21 C22 C23 C27 C28 C29 C33 C34 C35 C36 C37 C38 C39 C43 C44 C45: "CAP FILM 0.047UF 10% 1KVDC 5040", Case/Package=5040, Manufacturer=KEMET, Voltage=1kV
C14 C15 C16 C24 C25 C26 C30 C31 C32 C40 C41 C42: "CAP CER 2200PF 2KV X7R 2220", Case/Package=2220, Manufacturer=KEMET, Voltage=2kV
C56 C57 C58 C59 C65 C66 C67 C68: "CAP CER 2.2UF 50V X5R 0603", Capacitance=2.2μF, Case Code (Imperial)=0603, Case Code (Metric)=1608, Manufacturer=MURATA, Max Operating Temperature=85°C, Min Operating Temperature=-55°C, Ratings=AEC-Q200, TOLERANCE=20%, Voltage Rating=50V
C60 C61 C62 C63 C64: "CAP FILM 65UF 5% 1KVDC RADIAL", Case/Package=RADIAL, Manufacturer=KEMET, Voltage=1kV
HS1: "CUSTOM", Case/Package=N/A, Manufacturer=WOLFSPEED
J1: library part TSM-128-01-L-DV-A_DUAL_CUSTOM, Manufacturer=SAMTEC, Package=None
J2 J4 J6 J8: "BOX SCREW LUG 14-1/0 WIRE", Case/Package=N/A, Manufacturer=MCMASTER-CARR, Manufacturer Part Number=4164N12
J3 J5 J7 J9: "TERM REDCUBE M4 8PIN PCB", Case/Package=N/A, Current Rating=80A, Manufacturer="WURTH ELEKTRONIK", Manufacturer Print=WURTH, Max Operating Temperature=135°C, Min Operating Temperature=-40°C, Package Quantity=250, Supplier Part Number 1=1224952
MH1 MH2 MH3 MH4: "PLASTIC SPACER STUD METRIC THREA", Case/Package=N/A, Manufacturer="WURTH ELEKTRONIK", Manufacturer Part Number=971650485
Q1 Q2: library part GM3_HALF-BRIDGE, "MOSFET 4N-CH 1200V 100A", Case/Package=GMB, Manufacturer=WOLFSPEED, Manufacturer Part Number=CBB011M12GM4T
R1 R2 R7 R8 R9 R10 R11 R12 R49 R50 R51 R52 R53 R54 R55 R58: "RES SMD 10K OHM 1% 1/10W 0603", Case Code (Imperial)=0603, Case Code (Metric)=1608, Manufacturer=PANASONIC, Manufacturer Part Number=ERJ-3EKF1002V, Max Operating Temperature=155°C, Max Power Dissipation=0.1W, Min Operating Temperature=-55°C, Package Quantity=1, Power Rating=100mW, Resistance Tolerance=1%, Resistor Type="Thick Film", Supplier Part Number 1=1051156, Temperature Coefficient=100ppm/°C, Voltage Rating=75V
R3 R4 R5 R6 R56 R57 R59 R60: "RES SMD 10K OHM 1% 1/10W 0603", Case Code (Imperial)=0603, Case Code (Metric)=1608, Manufacturer=PANASONIC, Manufacturer Part Number=ERJ-3EKF1002V, Max Operating Temperature=155°C, Min Operating Temperature=-55°C, Package Quantity=1, Power Rating=100mW, Resistance Tolerance=1%, Resistor Type="Thick Film", Supplier Part Number 1=1051156, Temperature Coefficient=100ppm/°C, Voltage Rating=75V
R13 R14 R15 R16 R17 R18 R22 R23 R24 R25 R26 R27 R34 R35 R36 R40 R41 R42 R43 R44 R45 R46 R47 R48: "RES 220K OHM 1% 2W 2512", Ambient Temperature Range High=+70°C, Case/Package=2512, Manufacturer=TE, Package=CRGP2512, Power Rating=2W, Resistance=220kΩ, Temperature="-55°C to +155°C", Temperature Coefficient=±100ppm/°C, Temperature Range High=+155°C, Temperature Range Low=-55°C, TOLERANCE=0.01, Voltage Rating=500V
R19 R20 R21 R28 R29 R30 R31 R32 R33 R37 R38 R39: "RES 6.8 OHM 5% 1.5W 2512", Case/Package=2512, Manufacturer=STACKPOLE, POWER=1.5W
TP1 TP3 TP13 TP15: library part CMP-1672-00003-4, "PC TEST POINT MULTIPURPOSE BLACK", Case/Package=N/A, Manufacturer=KEYSTONE, Package Quantity=100
TP2 TP4 TP9 TP10: library part CMP-1672-00006-4, "PC TEST POINT MULTIPURPOSE YELLOW", Case/Package=N/A, Manufacturer=KEYSTONE, Package Quantity=100
TP5 TP6 TP11 TP12: library part CMP-1672-00002-4, "PC TEST POINT MULTIPURPOSE RED", Case/Package=N/A, Colour=Red, Manufacturer=KEYSTONE, Package Quantity=100
TP7 TP8 TP14 TP16: library part CMP-1672-00004-4, "PC TEST POINT MULTIPURPOSE WHITE", Case/Package=N/A, Manufacturer=KEYSTONE, Package Quantity=100
U1 U2 U3 U4: library part CMP-0384-01706-1, "IC CMOS 2 CIRCUIT 8MSOP", Amplifiers Per Package=2, Case/Package=8-TSSOP, Generic Part Number=AD8616, Input Bias Current=200fA, Input Offset Voltage=23uV, Manufacturer="ANALOG DEVICES"
U5 U6 U7 U8: "SENSOR CURRENT HALL 120A AC/DC", Case/Package=N/A, Manufacturer=LEM

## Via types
v1: diameter 27, hole 13, Top Layer to Bottom Layer, tented both sides, 347 vias

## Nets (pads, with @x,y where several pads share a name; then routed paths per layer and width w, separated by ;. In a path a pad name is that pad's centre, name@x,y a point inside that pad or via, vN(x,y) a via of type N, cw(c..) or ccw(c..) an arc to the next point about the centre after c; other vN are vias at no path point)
+2.5V_P-: C3.1 R1.1 R8.2 U1.5 | length 673.8
  Top Layer w10: C3.1@-5766.42,3618 -5767.37,3618 -5781.24,3631.86 -5781.24,3635.55 -5797.55,3651.86 -5849.33,3651.86 -5858.39,3660.92 -5858.39,3711.08 -5849.33,3720.14 -5849.33,3783.35 -5800.77,3831.91 -5760.14,3831.91 U1.5@-5758.66,3833.39 -5711.43,3833.39 -5647.68,3769.63 -5647.68,3746.73 -5599.9,3698.96 -5597.48,3698.96 -5586.34,3687.81 R1.1@-5586.34,3685.39 ; C3.1@-5752.52,3605.04 -5752.52,3597.99 -5704.53,3550 R8.2@-5703.62,3550
+2.5V_PB: C4.1 R2.1 R10.2 U2.5 | length 783.1
  Top Layer w10: v1(1880,3655) 1883.14,3651.86 1952.45,3651.86 1961.24,3643.08 1961.24,3642.98 1968.76,3635.46 1968.76,3631.86 1982.63,3618 1984.53,3618 1997.48,3605.04 1997.48,3597.99 2045.47,3550 R10.2@2046.38,3550 ; v1(1926.91,3831.91) 1989.86,3831.91 U2.5@1991.34,3833.39 ; v1(2135,3715) 2135,3711.47 2161.47,3685 R2.1@2163.66,3685
  Bottom Layer w10: v1(1880,3655) 1880,3720 1926.91,3766.91 v1(1926.91,3831.91) 2028.09,3831.91 2079.92,3780.08 2079.92,3770.08 v1(2135,3715)
+2.5V_S-: C52.1 R51.1 R55.2 U3.5 | length 394.7
  Top Layer w10: R51.1@-5766.38,-3550 R55.2@-5766.38,-3618 C52.1@-5766.42,-3686 C52.1@-5766.42,-3686 -5765.47,-3686 -5735,-3716.47 v1(-5735,-3720) ; v1(-5660,-3830) -5658.09,-3831.91 -5592.82,-3831.91 U3.5@-5591.34,-3833.39
  Bottom Layer w10: v1(-5735,-3720) -5660,-3795 v1(-5660,-3830)
+2.5V_SA: C54.1 R53.1 R58.2 U4.5 | length 517.3
  Top Layer w10: R53.1@1983.62,-3550 R58.2@1983.62,-3618 C54.1@1983.58,-3686 ; C54.1@1984.53,-3686 C54.1@1983.58,-3686 C54.1@1983.58,-3686 ; v1(2025,-3685) 1984.58,-3685 C54.1@1983.58,-3686 ; v1(2095,-3830) 2096.91,-3831.91 2157.18,-3831.91 U4.5@2158.66,-3833.39
  Bottom Layer w10: v1(2025,-3685) 2050,-3660 2085,-3660 2130,-3705 2130,-3745 2095,-3780 v1(2095,-3830)
+5V_P: C1.1 C2.1 C8.1 C10.1 C56.1 C57.1 C58.1 C59.1 J1.005 R1.2 R2.2 R7.2 R9.2 U1.8 U2.8 U5.1 U6.1 | length 1091.7
  Top Layer w10: v1(-5860,3578) -5856.75,3574.75 -5849.27,3574.75 -5824.53,3550 R7.2@-5823.62,3550 ; C1.1@-5823.58,3686 -5814.85,3694.73 v1(-5814.85,3734.85) ; v1@-5815,3735 -5813.88,3735 -5792.26,3756.61 U1.8@-5758.66,3756.61 ; R1.2@-5529.09,3685 -5530,3685 -5525,3690 v1(-5525,3725) ; C8.1@-5521.42,3482 -5517.52,3478.1 U6.1@-5517.52,3357.87 ; v1(-155,2590) -155,2570 -135,2550 J1.005@-97.44,2550 ; J1.005@-125,2570 v1(-125,2590) ; v1(-95,2590) -95,2552.44 J1.005@-97.44,2550 ; v1(-65,2590) -65,2570 -85,2550 J1.005@-97.44,2550 ; v1(1885,3540) 1921.38,3540 R9.2@1926.38,3545 ; C2.1@1926.42,3686 1935.15,3694.73 v1(1935.15,3734.85) ; v1@1935,3735 1936.12,3735 1957.74,3756.61 U2.8@1991.34,3756.61 ; R2.2@2220.91,3685 2220,3685 2225,3690 v1(2225,3725) ; C10.1@2228.58,3482 2235,3475.58 v1(2235,3445) 2233.74,3443.74 2233.74,3359.13 U5.1@2232.48,3357.87
  Bottom Layer w10: C59.1@-5766.42,3482 -5765.47,3482 -5738.25,3454.78 -5738.25,3438.25 v1(-5735,3435) ; C58.1@-5526.42,3482 -5520,3475.58 v1(-5520,3445) ; v1(1885,3540) 1911.61,3513.39 1911.61,3495.86 1925.47,3482 C57.1@1926.42,3482 ; C56.1@2223.58,3482 2235,3470.58 v1(2235,3445)
+5V_S: C46.1 C48.1 C53.1 C55.1 C65.1 C66.1 C67.1 C68.1 J1.107 R51.2 R52.2 R53.2 R54.2 U3.8 U4.8 U7.1 U8.1 | length 1182.4
  Top Layer w10: v1(-5855,-3515) -5855,-3518.62 R51.2@-5823.62,-3550 ; U8.1@-5832.48,-3357.87 -5832.48,-3473.1 C46.1@-5823.58,-3482 ; U3.8@-5591.34,-3756.61 -5560.95,-3756.61 -5543.25,-3738.92 -5543.25,-3733.25 v1(-5540,-3730) -5540,-3729.87 -5526.42,-3716.29 C53.1@-5526.42,-3686 ; R52.2@-5583.62,-3550 -5582.72,-3550 -5560.24,-3572.48 -5560.24,-3574.17 -5549.41,-3585 v1(-5485,-3585) ; v1(-150,-2590) J1.107@-150,-2570 ; v1(-120,-2590) -120,-2570 -100,-2550 J1.107@-97.44,-2550 ; v1(-90,-2590) -90,-2557.44 J1.107@-97.44,-2550 ; v1(-60,-2590) -60,-2570 -80,-2550 J1.107@-97.44,-2550 ; v1(1890,-3580) 1893.25,-3576.75 1898.73,-3576.75 1925.47,-3550 R53.2@1926.38,-3550 ; U7.1@1917.52,-3357.87 1918.76,-3359.11 1918.76,-3433.76 v1(1920,-3435) 1920,-3475.58 C48.1@1926.42,-3482 ; U4.8@2158.66,-3756.61 2161.44,-3756.61 2165,-3753.05 v1(2165,-3725) 2165,-3687.42 C55.1@2166.42,-3686 ; R54.2@2166.38,-3550 2167.28,-3550 2189.76,-3572.48 2189.76,-3574.17 2200.59,-3585 v1(2265,-3585)
  Bottom Layer w10: v1(-5830,-3440) -5830,-3444.6 -5823.58,-3451.02 C68.1@-5823.58,-3482 ; v1(-5575,-3435) -5570.69,-3435 -5548.76,-3456.92 -5548.76,-3460.61 -5527.37,-3482 C67.1@-5526.42,-3482 ; v1(1920,-3435) 1920,-3439.6 1926.42,-3446.02 C66.1@1926.42,-3482 ; v1(2120,-3435) 2120,-3436.53 2165.47,-3482 C65.1@2166.42,-3482
BLDP0: R22.2 R23.2 R24.2 R25.1 R26.1 R27.1
BLDP1: R16.2 R17.2 R18.2 R22.1 R23.1 R24.1
BLDP2: R13.2 R14.2 R15.2 R16.1 R17.1 R18.1
BLDS0: R34.1 R35.1 R36.1 R40.2 R41.2 R42.2
BLDS1: R40.1 R41.1 R42.1 R43.2 R44.2 R45.2
BLDS2: R43.1 R44.1 R45.1 R46.2 R47.2 R48.2
FB_P-: R3.2 R4.1 U1.6 | length 325.1
  Top Layer w10: U1.6@-5758.66,3807.8 -5757.18,3806.32 -5712.65,3806.32 -5680,3773.67 -5680,3665 -5658.7,3643.7 -5658.7,3630.33 R3.2@-5646.38,3618 R4.1@-5583.62,3618
FB_PB: R5.2 R6.1 U2.6 | length 328.9
  Top Layer w10: U2.6@1991.34,3807.8 1992.82,3806.32 2043.68,3806.32 2075,3775 2103.62,3746.38 R5.2@2103.62,3618 R6.1@2166.38,3618
FB_S-: R56.1 R57.2 U3.6 | length 300.2
  Top Layer w10: U3.6@-5591.34,-3807.8 -5592.82,-3806.32 -5633.45,-3806.32 -5647.68,-3792.09 -5647.68,-3712.17 -5646.38,-3710.87 R56.1@-5646.38,-3618 R57.2@-5583.62,-3618
FB_SA: R59.1 R60.2 U4.6 | length 327.9
  Top Layer w10: U4.6@2158.66,-3807.8 2157.18,-3806.32 2113.86,-3806.32 2071.5,-3763.96 2071.5,-3707.43 2089.76,-3689.17 2089.76,-3630.96 2102.72,-3618 R60.2@2166.38,-3618
G1_P: J1.034 Q1.G1
G1_S: J1.092 Q2.G1
G2_P: J1.043 Q1.G2
G2_S: J1.099 Q2.G2
G3_P: J1.020 Q1.G3
G3_S: J1.075 Q2.G3
G4_P: J1.013 Q1.G4
G4_S: J1.070 Q2.G4
GND_P: C1.2 C2.2 C3.2 C4.2 C5.2 C6.2 C7.2 C8.2 C9.2 C10.2 C56.2 C57.2 C58.2 C59.2 J1.006 R8.1 R10.1 R11.1 R12.1 U1.4 U2.4 U5.2 U6.2 | length 1540.9
  Top Layer w10: v1(-5860,3615) -5826.62,3615 C3.2@-5823.58,3618 ; C7.2@-5823.58,3482 -5822.63,3482 -5808.76,3468.14 -5808.76,3467.19 -5808.25,3466.68 -5808.25,3443.25 v1(-5805,3440) ; C1.2@-5766.42,3686 -5765,3687.42 v1(-5765,3724.26) ; v1(-5696.25,3446.25) -5696.25,3474.63 R11.1@-5703.62,3482 -5702.72,3482 -5680.24,3504.48 -5680.24,3506.17 -5661.24,3525.17 -5661.24,3536.14 -5647.37,3550 R8.1@-5646.38,3550 ; U6.2@-5596.26,3357.87 -5596.26,3465.27 -5579.53,3482 C8.2@-5578.58,3482 ; U1.4@-5591.34,3833.39 -5540.59,3833.39 -5528.4,3821.2 v1(-5523.8,3821.2) ; C5.2@-5521.42,3550 v1(-5490,3550) ; v1(10,2545) 40.12,2545 50.12,2555 92.44,2555 J1.006@97.44,2550 144.88,2550 168.38,2573.5 183.5,2573.5 v1(185,2575) ; v1(10,2575) 13.25,2571.75 23.56,2571.75 25.31,2570 30,2570 35,2565 35,2550 J1.006@50.12,2550 ; J1.006@102.56,2555 144.88,2555 154.88,2545 v1(185,2545) ; v1(1885,3580) 1888.25,3583.25 1895.73,3583.25 1923.02,3610.55 C4.2@1923.02,3615.55 ; C9.2@1926.42,3477 1927.37,3477 1941.24,3463.14 1941.24,3448.36 1950,3439.6 v1(1950,3435) ; C2.2@1983.58,3686 1994.4,3675.18 2015.22,3675.18 2020.4,3670 v1(2025,3670) ; v1(2045,3445) 2045,3480.62 R12.1@2046.38,3482 2047.28,3482 2069.76,3504.48 2069.76,3506.17 2088.76,3525.17 2088.76,3536.14 2102.63,3550 R10.1@2103.62,3550 ; U5.2@2153.74,3357.87 2154.37,3358.5 2154.37,3439.37 v1(2155,3440) 2155,3468.14 2168.86,3482 C10.2@2171.42,3482 ; U2.4@2158.66,3833.39 2192.26,3833.39 2208.88,3850 v1(2210,3850) ; C6.2@2228.58,3550 v1(2260,3550)
  Bottom Layer w10: C59.2@-5823.58,3482 -5822.63,3482 -5808.76,3468.14 -5808.76,3467.19 -5808.25,3466.68 -5808.25,3443.25 v1(-5805,3440) ; v1(-5595,3445) -5595,3470.58 C58.2@-5583.58,3482 ; v1(1950,3435) 1950,3437.78 1968.76,3456.54 1968.76,3468.14 1982.63,3482 C57.2@1983.58,3482 ; v1(2155,3440) 2155,3470.58 C56.2@2166.42,3482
